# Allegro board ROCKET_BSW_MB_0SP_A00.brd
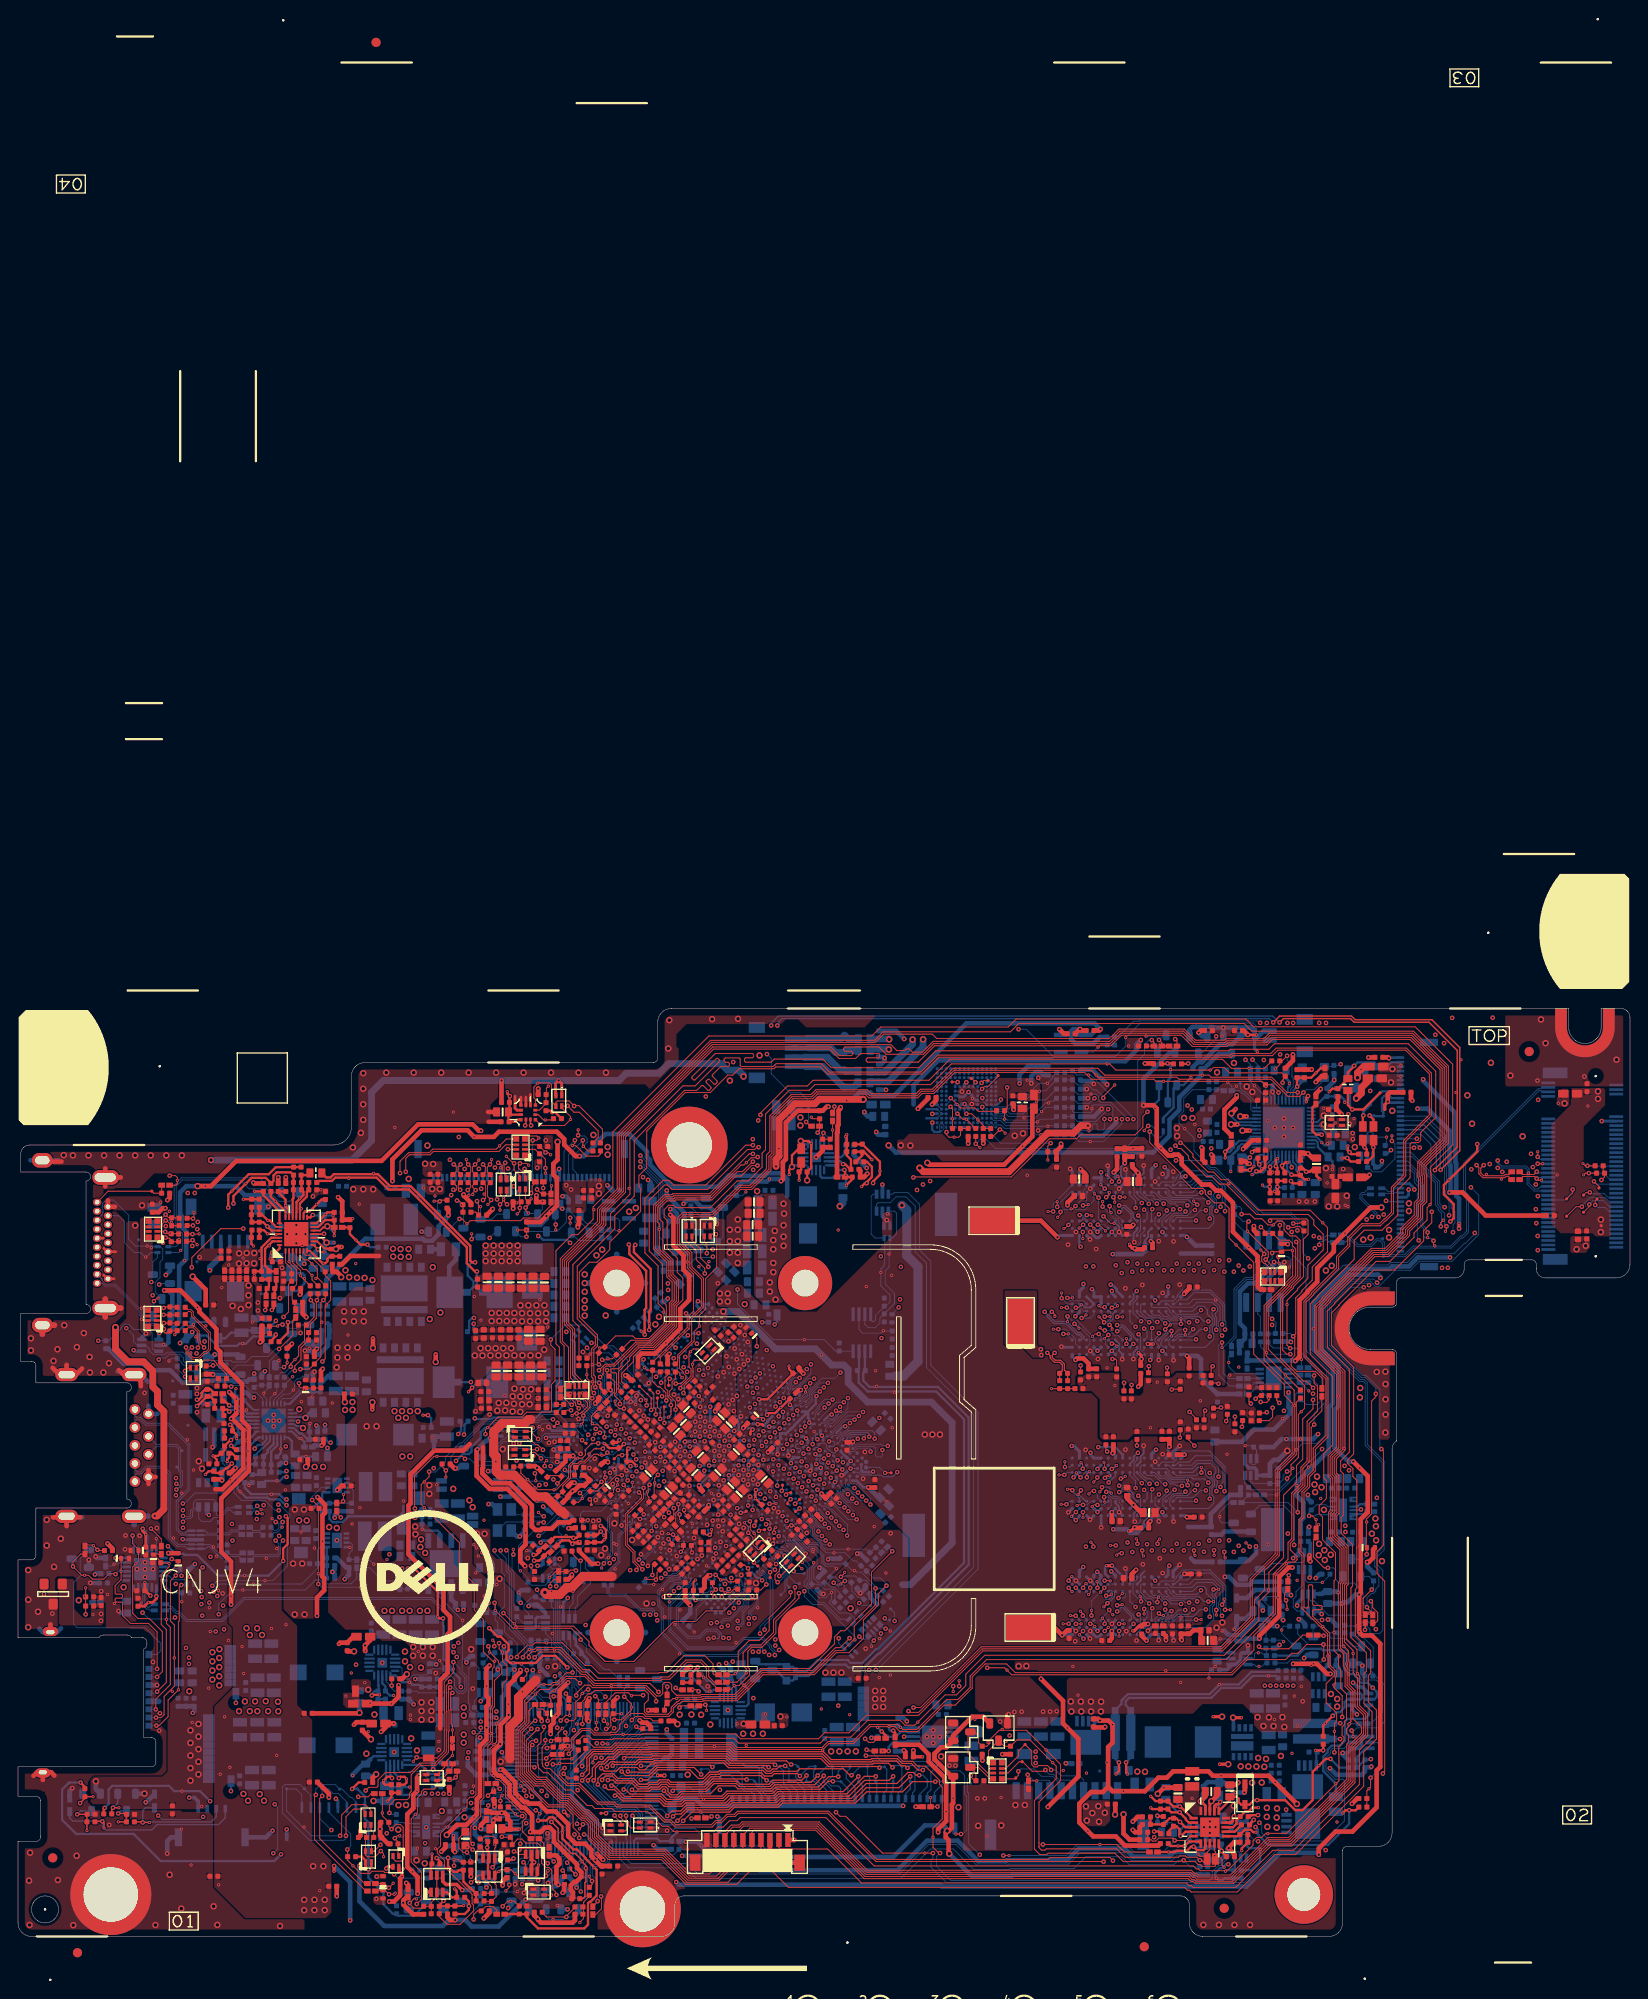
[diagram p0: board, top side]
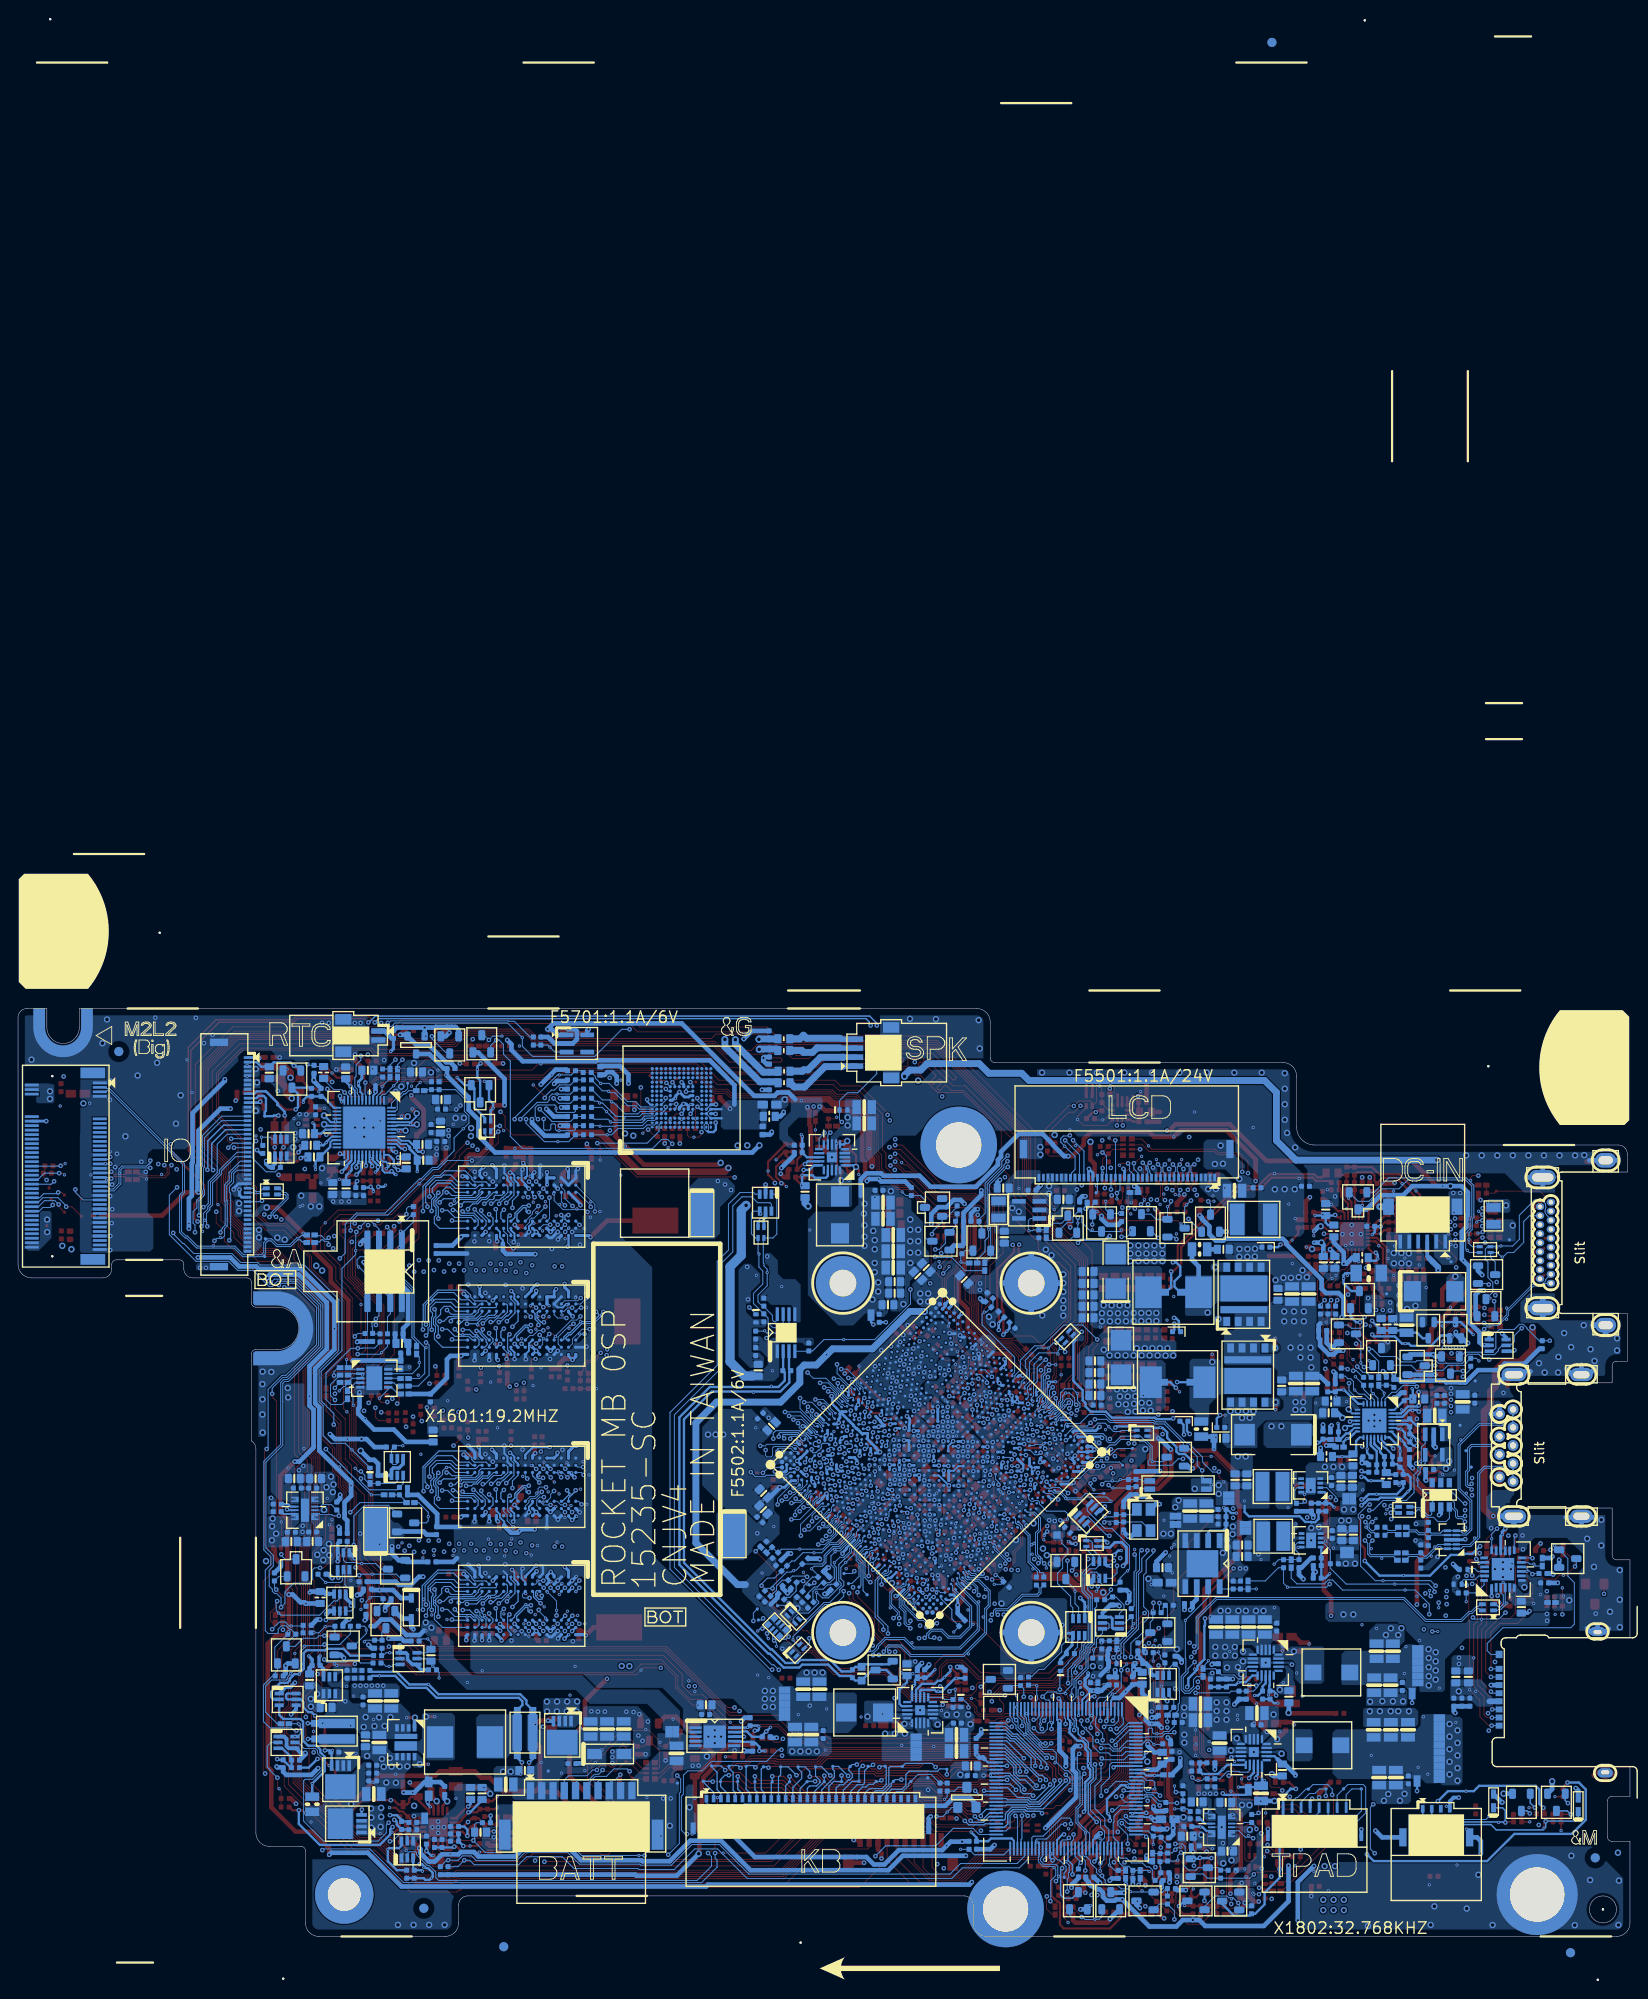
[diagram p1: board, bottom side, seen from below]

Outline 178.9 x 103 mm; copper layers: TOP, L2GND, L3, L4, L5VCC, BOTTOM. Coordinates in mm from the lower left corner of the outline.
Outline path: 0,41.8 0,33.15 8.99,33.15 arc(9.18,33.37) 9.45,33.46 12.15,33.46 arc(12.42,33.37) 12.61,33.15 13.8,33.15 arc(14.15,33.01) 14.3,32.66 14.3,32.38 arc(14.2,32.08) 13.95,31.9 13.95,22.07 14.8,22.07 arc(15.15,21.93) 15.3,21.58 15.3,19.34 arc(15.15,18.99) 14.8,18.85 0,18.85 0,15.55 2,15.55 arc(2.35,15.4) 2.5,15.05 2.5,11.05 arc(2.35,10.7) 2,10.55 0,10.55 0,1.5 arc(0.44,0.44) 1.5,0 71.4,0 arc(72.46,0.44) 72.9,1.5 72.9,3.5 arc(73.19,4.21) 73.9,4.5 129,4.5 arc(129.71,4.21) 130,3.5 130,1.5 arc(130.44,0.44) 131.5,0 145.5,0 arc(146.56,0.44) 147,1.5 147,9.5 arc(147.15,9.85) 147.5,10 151,10 arc(152.06,10.44) 152.5,11.5 152.5,54.13 arc(152.63,54.63) 153,55 153,64.65 arc(152.85,65) 152.5,65.15 150.09,65.15 arc(147.74,67.5) 150.09,69.85 152.5,69.85 arc(152.85,70) 153,70.35 153,72.6 arc(153.15,72.95) 153.5,73.1 159.5,73.1 arc(160.21,73.39) 160.5,74.1 160.5,74.6 arc(160.65,74.95) 161,75.1 168,75.1 arc(168.35,74.95) 168.5,74.6 168.5,74.1 arc(168.79,73.39) 169.5,73.1 177.4,73.1 arc(178.46,73.54) 178.9,74.6 178.9,102 arc(178.61,102.71) 177.9,103 175.7,103 175.7,100.9 arc(173.9,99.1) 172.1,100.9 172.1,103 72.5,103 arc(71.44,102.56) 71,101.5 71,97.5 arc(70.85,97.15) 70.5,97 38.5,97 arc(37.44,96.56) 37,95.5 37,89.85 arc(36.41,88.44) 35,87.85 1.3,87.85 arc(0.59,87.56) 0.3,86.85 0.3,84.85 7.55,84.85 arc(8.05,84.35) 7.55,83.85 7.55,70.15 arc(8.05,69.65) 7.55,69.15 0.3,69.15 0.3,63.85 1.48,63.85 arc(1.83,63.7) 1.98,63.35 1.98,61.45 12.08,61.45 arc(12.58,60.95) 12.08,60.45 12.08,48.55 arc(12.58,48.05) 12.08,47.55 1.98,47.55 1.98,42.3 arc(1.83,41.95) 1.48,41.8 0,41.8 ; 1.5,3 arc(3,4.5) 4.5,3 arc(3,1.5) 1.5,3 ; 7.3,4.65 arc(10.3,7.65) 13.3,4.65 arc(10.3,1.65) 7.3,4.65 ; 66.8,3.05 arc(69.3,5.55) 71.8,3.05 arc(69.3,0.55) 66.8,3.05 ; 72,87.85 arc(74.5,90.35) 77,87.85 arc(74.5,85.35) 72,87.85 ; 140.9,4.65 arc(142.7,6.45) 144.5,4.65 arc(142.7,2.85) 140.9,4.65

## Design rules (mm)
constraint set DEFAULT: min track width 0.127, pair gap 0.102
net group CHARGER_10MIL_VIA_25MIL: nets PWR_CHG_CSON_1 PWR_CHG_CSOP_1
net group CLK-MW: nets PCH_SUSCLK PCH_SUSCLK_KBC
net group COMP_DRAM: nets DRAM_RCOMP_1 SM_RCOMP_0
net group EDP_AUX_CON_N: nets EDP_AUX_CON_N EDP_AUX_CPU_N
net group EDP_AUX_CON_P: nets EDP_AUX_CON_P EDP_AUX_CPU_P
net group EDP_TX_CON_N0: nets EDP_TX_CON_N0 EDP_TX_CPU_N0
net group EDP_TX_CON_N1: nets EDP_TX_CON_N1 EDP_TX_CPU_N1
net group EDP_TX_CON_P0: nets EDP_TX_CON_P0 EDP_TX_CPU_P0
net group EDP_TX_CON_P1: nets EDP_TX_CON_P1 EDP_TX_CPU_P1
net group EMMC_CMD: nets EMMC_CMD EMMC_CMD_R
net group EMMC_DATA_0: nets EMMC_DATA_0 EMMC_DATA_0_R
net group EMMC_DATA_1: nets EMMC_DATA_1 EMMC_DATA_1_R
net group EMMC_DATA_2: nets EMMC_DATA_2 EMMC_DATA_2_R
net group EMMC_DATA_3: nets EMMC_DATA_3 EMMC_DATA_3_R
net group EMMC_DATA_4: nets EMMC_DATA_4 EMMC_DATA_4_R
net group EMMC_DATA_5: nets EMMC_DATA_5 EMMC_DATA_5_R
net group EMMC_DATA_6: nets EMMC_DATA_6 EMMC_DATA_6_R
net group EMMC_DATA_7: nets EMMC_DATA_7 EMMC_DATA_7_R
net group EMMC_RCLK: nets EMMC_RCLK EMMC_RCLK_R
net group HDA-MW: nets HDA_CODEC_RST#_CTRL HDA_SPKR
net group HDA_BITCLK_CODEC: nets HDA_BITCLK_CODEC HDA_BITCLK_CPU
net group HDA_RST#_CODEC: nets HDA_RST#_CODEC HDA_RST#_CPU
net group HDA_SDIN0_CODEC: nets HDA_SDIN0_CODEC HDA_SDIN0_CPU
net group HDA_SDOUT_CODEC: nets HDA_SDOUT_CODEC HDA_SDOUT_CPU
net group HDA_SYNC_CODEC: nets HDA_SYNC_CODEC HDA_SYNC_CPU
net group HDMI_DATA_CON_N0: nets HDMI_DATA_CON_N0 HDMI_DATA_CPU_N0
net group HDMI_DATA_CON_N1: nets HDMI_DATA_CON_N1 HDMI_DATA_CPU_N1
net group HDMI_DATA_CON_N2: nets HDMI_DATA_CON_N2 HDMI_DATA_CPU_N2
net group HDMI_DATA_CON_N3: nets HDMI_DATA_CON_N3 HDMI_DATA_CPU_N3
net group HDMI_DATA_CON_P0: nets HDMI_DATA_CON_P0 HDMI_DATA_CPU_P0
net group HDMI_DATA_CON_P1: nets HDMI_DATA_CON_P1 HDMI_DATA_CPU_P1
net group HDMI_DATA_CON_P2: nets HDMI_DATA_CON_P2 HDMI_DATA_CPU_P2
net group HDMI_DATA_CON_P3: nets HDMI_DATA_CON_P3 HDMI_DATA_CPU_P3
net group INT_SERIRQ: nets INT_SERIRQ LPC_SERIRQ_CPU
net group LPC_AD_CPU_P0: nets LPC_AD_CPU_P0 LPC_AD_CPU_R_P0
net group LPC_AD_CPU_P1: nets LPC_AD_CPU_P1 LPC_AD_CPU_R_P1
net group LPC_AD_CPU_P2: nets LPC_AD_CPU_P2 LPC_AD_CPU_R_P2
net group LPC_AD_CPU_P3: nets LPC_AD_CPU_P3 LPC_AD_CPU_R_P3
net group LPC_CLK_CPU_P0: nets LPC_CLK_CPU_P0 LPC_CLK_LPC
net group LPC_CLK_CPU_P1: nets LPC_CLK_CPU_P1 LPC_CLK_KBC
net group LPC_FRAME#_CPU: nets LPC_FRAME#_CPU LPC_FRAME#_CPU_R
net group PCIE_RX_CPU_N0: nets PCIE_RX_CPU_N0 WLANTX_N3
net group PCIE_RX_CPU_P0: nets PCIE_RX_CPU_P0 WLANTX_P3
net group PCIE_TX_CON_N0: nets PCIE_TX_CON_N0 PCIE_TX_CPU_N0
net group PCIE_TX_CON_P0: nets PCIE_TX_CON_P0 PCIE_TX_CPU_P0
net group POWER_10_VCCTSEN: nets PWR_VCC0_TSEN PWR_VCC0_TSEN1
net group POWER_10_VIA_20: nets PWR_VCC0_CSCOMP PWR_VCC0_CSMP1
net group POWER_12: nets CARD_AV18 SDREG
net group PSID_4M: nets PS_ID PSID_EC
net group SD_MMC_CLK/MS_DATA2: nets SD_MMC_CLK/MS_DATA2 SP5
net group SENSOR: nets GSEN2_INT1 GSEN2_INT2
net group SPI_HOLD_CPU: nets SPI_HOLD_CPU SPI_HOLD_ROM
net group SPI_SI_CPU: nets SPI_SI_CPU SPI_SI_ROM
net group SPI_SO_CPU: nets SPI_SO_CPU SPI_SO_ROM
net group SPI_WP_CPU: nets SPI_WP_CPU SPI_WP_ROM
net group T8: nets VD_IN1 VD_IN1_C
net group THERM_10MIL: nets VD1_EN# VD_OUT1#
net group USB30_TX_CMC_N0: nets USB30_TX_CMC_N0 USB30_TX_CPU_N0
net group USB30_TX_CMC_P0: nets USB30_TX_CMC_P0 USB30_TX_CPU_P0
net group USB_CON_PN0: nets USB_CON_PN0 USB_CPU_PN0
net group USB_CON_PN1: nets USB_CON_PN1 USB_CPU_PN1
net group USB_CON_PN2: nets USB_CON_PN2 USB_CPU_PN2
net group USB_CON_PN4: nets USB_CON_PN4 USB_CPU_PN4
net group USB_CON_PP0: nets USB_CON_PP0 USB_CPU_PP0
net group USB_CON_PP1: nets USB_CON_PP1 USB_CPU_PP1
net group USB_CON_PP2: nets USB_CON_PP2 USB_CPU_PP2
net group USB_CON_PP4: nets USB_CON_PP4 USB_CPU_PP4
net group 3V_5V_10MIL: nets PWR_3D3V_FB PWR_3D3V_VOUT PWR_5V_FB PWR_5V_FB_A PWR_5V_VOUT
net group 3V_5V_20MIL: nets PWR_3D3V_BOOT_A PWR_5V_BOOT_A PWR_5V_VCC
net group BKLT_EDP-MW: nets BKLT_CTRL EC_BRIGHTNESS L_BKLT_CTRL L_BKLT_CTRL_B L_BKLT_CTRL_CPU LCD_BRIGHTNESS LVDS_VDD_EN LVDS_VDD_EN_B LVDS_VDD_EN_CPU LVDS_VDD_EN_R
net group CHARGER_10MIL: nets BOOST_MODE# PWR_CHG_CMPIN_R PWR_CHG_CMPIN_RR PWR_CHG_IFAULT PWR_CHG_ILIM PWR_CHG_IOUT
net group CHARGER_20MIL: nets PWR_CHG_BTST_R
net group CLK_19D2M_CPU-MW: nets ICLKICOMP ICLKRCOMP XTL_19D2M_X1_CPU XTL_19D2M_X2_CPU
net group CLK_CARD: nets 12MHZ_IN
net group CLK_FST_SPI-MW: nets SPI_CLK_CPU_MUX SPI_CLK_KBC SPI_CLK_KBC_MUX SPI_CLK_KBC_R SPI_CLK_ROM_MUX
net group CLK_SVID-MW: nets CPU_VSS2 CPU_VSS16 VIDSCK_CORE VIDSCK_CPU VIDSCK_CPU_R VIDSCK_GFX
net group COMP_10: nets GPIO_RCOMP18 RCOMP_LPC_HVT SDMMC1_RCOMP SDMMC3_RCOMP
net group COMP_HSIC: nets USB_HSIC_RCOMP
net group COMP_MCSI-MW: nets MCSI_COMP
net group COMP_USB: nets USB_RCOMP
net group CPU_SIDE-MW: nets 1D35V_VTT_PWRGD AC_PRESENT_CPU AC_PRESENT_KBC AD_IA CFG0 CFG1 CFG2 CFG3 CFG4 CFG5 CFG6 CFG7 CFG8 COREPWROK DBC_EN DBC_EN_C DBC_EN_R DDR3_DRAM_PWROK DDR3_DRAM_PWROK_D DDR3_VCCA_PWRGD DDR3_VCCA_PWRGD_G DRAM_SEL0 DRAM_SEL1 DRAM_SEL2 ECSMI#_KBC EDM_SOC EDP_HPD_CPU FFS_INT2_CPU GP_CAMERASB00 GP_CAMERASB01 GP_CAMERASB02 GP_CAMERASB03 GP_CAMERASB04 GP_CAMERASB05 GP_CAMERASB06 GP_CAMERASB07 GP_CAMERASB08 GP_CAMERASB09 GP_CAMERASB11 GPIO_ALERT GPIO_SUS0 GPIO_SUS1 GPIO_SUS2 GPIO_SUS3 GPIO_SUS4 H_PROCHOT# HDD_FALL_INT_C HDMI_HPD_G HDMI_PCH_DET# HPD_HDMI_CON INT_TP# INT_TP#_CONN L_BKLT_EN L_BKLT_EN_CPU ME_FWP_SOC ME_UNLOCK# PCU_SMB_ALERT# PEG_CLKREQ0_CPU# PEG_CLKREQ0_D PEG_CLKREQ0_WLAN# PEG_CLKREQ1_CPU# PEG_CLKREQ2_CPU# PEG_CLKREQ3_CPU# PLT_RST# PLT_RST#_CPU_G PLT_RST#_D PLTRST# PLTRST#_CPU PLTRST#_CPU_D PM_PCIE_WAKE# PM_PWRBTN# PM_PWRBTN#_CPU PM_RSMRST# PM_SLP_S0IX# PM_SLP_S3# PM_SLP_S3#_CPU PM_SLP_S3#_CPU_D PM_SLP_S4# PM_SLP_S4#_CPU PM_SLP_S4#_CPU_D PM_SUS_STAT#_CPU PMC_BATLOW# PMC_RSTBTN# PROCHOT#_CPU PROCHOT#_EC PWR_1D35V_PGOOD PWR_GFX_VRHOT# PWR_VCORE_VRHOT# Q3601_2 Q3615_G RSMRST#_KBC RSMRST#_KBC_G RSMRST#_KBC_MUX RSVD_VSS#A3 RTC_INTRUDER RUN_ON# RUN_ON_R SATA_RXN0 SATA_RXN1 SATA_RXP0 SATA_RXP1 SEC_GPIO_SUS8 SEC_GPIO_SUS9 SEC_GPIO_SUS10 SENSOR_HUB_RST#_R SM_DRAMRST# SOC_EXTSMI_N SOC_RUNTIME_SCI# SOC_RUNTIME_SCI#_KBC SPI_CS_CPU_MUX SPI_CS_KBC_MUX SPI_CS_KBC_N0 SPI_CS_KBC_R_N0 SPI_CS_ROM_MUX SPI_SI_KBC SPI_SI_KBC_R SPI_SO_KBC SUS_PWR_ACK_R SUS_PWRDN_ACK SUS_PWRDN_ACK_CPU SYS_PWROK SYS_PWROK_G UART1_CTS UART1_RTS UART1_RX UART1_RXD UART1_TX UART1_TXD USB_OTG_ID USB_VBUSSNS VSS5 XDP_PREQ# XDP_TCK XDP_TDI XDP_TDO XDP_TMS XDP_TRST#
net group DDR3_CHA_CMD-MW: nets M_A_A0 M_A_A1 M_A_A2 M_A_A3 M_A_A4 M_A_A5 M_A_A6 M_A_A7 M_A_A8 M_A_A9 M_A_A10 M_A_A11 M_A_A12 M_A_A13 M_A_A14 M_A_A15 M_A_BS0 M_A_BS1 M_A_BS2 M_A_CAS# M_A_RAS# M_A_WE#
net group DDR3_CHA_CTRL-MW: nets M_A_CKE0 M_A_CS#0 M_A_DIM0_ODT0
net group DDR3_CHA_DATA-MW: nets M_A_DM0 M_A_DM1 M_A_DM2 M_A_DM3 M_A_DM4 M_A_DM5 M_A_DM6 M_A_DM7 M_A_DQ0 M_A_DQ1 M_A_DQ2 M_A_DQ3 M_A_DQ4 M_A_DQ5 M_A_DQ6 M_A_DQ7 M_A_DQ8 M_A_DQ9 M_A_DQ10 M_A_DQ11 M_A_DQ12 M_A_DQ13 M_A_DQ14 M_A_DQ15 M_A_DQ16 M_A_DQ17 M_A_DQ18 M_A_DQ19 M_A_DQ20 M_A_DQ21 M_A_DQ22 M_A_DQ23 M_A_DQ24 M_A_DQ25 M_A_DQ26 M_A_DQ27 M_A_DQ28 M_A_DQ29 M_A_DQ30 M_A_DQ31 M_A_DQ32 M_A_DQ33 M_A_DQ34 M_A_DQ35 M_A_DQ36 M_A_DQ37 M_A_DQ38 M_A_DQ39 M_A_DQ40 M_A_DQ41 M_A_DQ42 M_A_DQ43 M_A_DQ44 M_A_DQ45 M_A_DQ46 M_A_DQ47 M_A_DQ48 M_A_DQ49 M_A_DQ50 M_A_DQ51 M_A_DQ52 M_A_DQ53 M_A_DQ54 M_A_DQ55 M_A_DQ56 M_A_DQ57 M_A_DQ58 M_A_DQ59 M_A_DQ60 M_A_DQ61 M_A_DQ62 M_A_DQ63
net group DDR3L_ZQ: nets VRAM_CH_A_ZQ_1A VRAM_CH_A_ZQ_2A VRAM_CH_A_ZQ_3A VRAM_CH_A_ZQ_4A
net group EMMC_CLK: nets EMMC_CLK EMMC_CLK_L EMMC_CLK_R
net group EMMC_DATA_CMD: nets EMMC_E9 EMMC_E10 EMMC_F10 EMMC_K10 EMMC_RESET# EMMC_RESET#_R EMMC_VDDI
net group GND_100: nets EC_AGND
net group HDMI_DDC-MW: nets HDMI_CLK_CON HDMI_CLK_CPU HDMI_DATA_CON HDMI_DATA_CPU
net group KB: nets KCOL0 KCOL1 KCOL2 KCOL3 KCOL4 KCOL5 KCOL6 KCOL7 KCOL8 KCOL9 KCOL10 KCOL11 KCOL12 KCOL13 KCOL14 KCOL15 KCOL16 KROW0 KROW1 KROW2 KROW3 KROW4 KROW5 KROW6 KROW7
net group LED: nets AMBER_LED_BAT BAT_AMBER BAT_WHITE BATT_WHITE_LED_R# CHG_AMBER_LED_R# D_BAT_AMBER D_BAT_WHITE WHITE_LED_BAT
net group M_A_CLK0: nets M_A_CLK0_L
net group OTHER_4: nets 1D05V_PWRGD 1D5V_S0_EN 1D05V_VNN_EN 1D05V_VNN_PG_G 1D05V_VNN_PWRGD 1D8V_S0_EN 1D8V_S5_PG 1D24V_S5_PG 3D3V_S5_PRIME_EN 3D3V_S5_PRIME_PG 3D3V_S5_PRIME_PG_1 3V_5V_EN 3V_5V_POK 5V_DDC_HDMI1 5V_DDC_HDMI2 AC_IN# AC_IN_KBC# AD_IA_HW AD_IA_HW2 ALERT# ALL_SYS_PWRGD ALS_INT# AMP_MUTE# BAT_IN# BLON_OUT BLON_OUT_C BLUETOOTH_EN CAMERA_DET# CAP_LED CAP_LED# CAP_LED_Q CAP_LED_R# COMBO-GPI DP_HPD0_C DP_HPD0_G E51_RX1 E51_RX2 E51_TX1 E51_TX2 E51_TXD EAPD# ECRST# GFX_PWRGD GSENSOR_CS GSENSOR_SDO H_A20GATE H_RCIN# HALL_KB_DIS# HDMI_IN# IMVP_PWRGD INT_SERIRQ_OE KB_LOOP KBC_BEEP KBC_ON#_GATE KBC_ON#_GATE_L KBC_PECI KBC_PWRBTN# LCD_TST LCD_TST_C LCD_TST_EN LCD_TST_KBC LID_CLOSE# LVDS_VDD_EN_KBC MODEL_ID MODEL_ID_AD NCT3956_OE#_MUX PBAT_PRES1# PCB_VER_AD PQ3802_1 PQ4008_2 PQ4008_6 PQ4405_2 PQ4405_3 PQ4405_5 PQ4405_6 PQ4406_D PQ4406_G PQ4408_C PQ4408_E PSID_DISABLE#_R_C PSL_IN1# PSL_IN2# PSL_OUT# PURE_HW_SHUTDOWN# PWR_1D05V_PWR_EN PWR_1D8V_S5_EN PWR_1D15V_PG PWR_1D15V_S5_EN PWR_1D24V_EN PWR_1D35V_EN PWR_3D3V_EN PWR_3D3V_EN1 PWR_3V_PG PWR_5V_EN1 PWR_5V_PG RTC_DET# SD_CD# SD_CD#_CARD SD_WP#/MS_DATA1_C SENSOR_KB_DIS SIO_SLP_S4 SLEEVE_CTRL SUSPWRDNACK_SOC_EC SYS_PRES1# T_CRIT# THERM_SYS_SHDN# TOUCH_PANEL_EN TP_DISABLE# TP_DISABLE#_R TP_ON# TP_ON#_GATE USB_OC#0 USB_OC#1 USB_PWR_EN# VOL_DOWN# VOL_UP# WIFI_RF_EN
net group OTHER_6: nets S5_ENABLE
net group OTHER_10: nets KBC_VBKUP M_VREF_DQ_DIM0 V_SM_VREF_CNT
net group OTHER_12: nets CPVEE LDO1_CAP LDO2_CAP LDO3_CAP
net group P27_AUDIO_40M: nets AUD_SPK_L+ AUD_SPK_L+_C AUD_SPK_L- AUD_SPK_L-_C AUD_SPK_R+ AUD_SPK_R+_C AUD_SPK_R- AUD_SPK_R-_C
net group P27_AUDIO_ANALOG: nets AUD_HP1_JACK_L AUD_HP1_JACK_L1 AUD_HP1_JACK_R AUD_HP1_JACK_R1 AUD_PC_BEEP AUD_PC_BEEP_C AUD_PORTA_L_R_B AUD_PORTA_R_R_B AUD_SENSE AUD_SENSE_A AUD_VREF CBN CBP HDA_SPKR_R JACK_PLUG KBC_BEEP_R LINE1-L_C LINE1-L_R LINE1_L LINE1_R LINE1_VREFO_L LINE1_VREFO_R
net group POWER_8: nets Q6204_S
net group POWER_10: nets 1D05V_PWR_BS 1D05V_PWR_BS_R 1D05V_PWR_BYP 1D05V_PWR_FB 1D05V_PWR_FBH 1D05V_PWR_FBL 1D05V_PWR_LDO 3D3V_GSEN2 3D3V_S0_CT 5V_PWR_2 5V_S0_CT +3V_1D5V_AVDD +3V_AVDD BATT_WHITE_LED# CHG_AMBER_LED# CPVREF DVDD_1D5V MIC_CAP PU4902_S5 PU4902_VCNTL PWR_1D05V_PWR_ILIM PWR_1D8V_FB PWR_1D15V_FB PWR_1D24V_FB\ PWR_1D35V_BYP PWR_1D35V_IMAX PWR_1D35V_LDO_P5 PWR_1D35V_VFB PWR_3D3V_EN2 PWR_3D3V_FB2 PWR_5V_EN2 PWR_5V_LDO PWR_CHG_ACDET PWR_CHG_ACN PWR_CHG_ACOK PWR_CHG_ACP PWR_CHG_BTST PWR_CHG_CMPIN PWR_CHG_REGN PWR_VCC0_COMP PWR_VCC0_COMP1 PWR_VCC0_COMP2 PWR_VCC0_DIFFOUT PWR_VCC0_FB PWR_VCC0_ILIM PWR_VCC0_IMAX PWR_VCC0_PVCC PWR_VCC0_ROSC PWR_VCC0_VBOOT/ADDR PWR_VCC0_VCC PWR_VCC0_VRMP PWR_VGG_COMP PWR_VGG_COMP1 PWR_VGG_COMP2 PWR_VGG_CSCOMP PWR_VGG_CSMP1 PWR_VGG_DIFFOUT PWR_VGG_FB PWR_VGG_ILIM PWR_VGG_IMAX PWR_VGG_IOUT PWR_VGG_PVCC PWR_VGG_ROSC PWR_VGG_TSEN PWR_VGG_TSEN1 PWR_VGG_VBOOT/ADDR PWR_VGG_VCC PWR_VGG_VRMP Q6205_D Q6206_D TP_VDD VCC_VCORE1_SENSE VSS_VCORE1_SENSE VSS_VNN_SENSE VTT_CT_1D8VC VTT_CT_3D3V_S5_PRIME VTT_EN
net group POWER_10_VCCI: nets PWR_VCC0_IOUT
net group POWER_10_VIA: nets AD+_G_1 AD+_G_2 DC_IN_D PWR_CHG_SRN PWR_CHG_SRP
net group POWER_10M_POWER: nets AD_OFF_L AD_OFF_R PQ4209_D PWR_CHG_AD_OFF PWR_CHG_AD_OFF_R PWR_CHG_CMPOUT
net group POWER_20: nets 0D675V_S0_DISCHG 1D5V_BRI_S0 1D5V_DIS_Q +RTC_PWR +VCHGR_R BOOST_MON_1 EC_AVCC EC_VTT KBC_VCORF PD4403_A PD4403_K PU4401_6 PWR_GFX_SNUB PWR_VCORE_SNUB
net group POWER_40: nets PWR_VGG_BT VREF_DQ VREF_DQ_R1203
net group POWER_40_ULP: nets PWR_CHG_HIDRV
net group POWER_600_VIA: nets DCBATOUT_R
net group RTC-MW: nets BVCCRTC_EXTPAD
net group SMBUS_CLK-MW: nets BAT_SCL DMIC_CLK DMIC_CLK_C DMIC_CLK_R NCT_CLK PBAT_SMBCLK1 PWR_CHG_BAT_SCL SENSOR_I2C_SCL SENSOR_I2C_SCL_ALS SIO_I2C5_CLK SMB_CLK SML1_CLK TP_CLK TP_CLK_C TP_I2C_CLK TP_I2C_CLK_D TPCLK
net group SMBUS_DAT-MW: nets BAT_SDA DMIC_DATA DMIC_DATA_C DMIC_DATA_R NCT_DATA PBAT_SMBDAT1 PWR_CHG_BAT_SDA SENSOR_I2C_SDA SENSOR_I2C_SDA_ALS SIO_I2C5_DATA SMB_DATA SML1_DATA TP_DAT TP_DATA_C TP_I2C_DATA TP_I2C_DATA_D TPDATA
net group SPI_CLK_CPU: nets SPI_CLK_CPU SPI_CLK_ROM SPI_CLK_ROM_R
net group SPI_CS_CPU_N0: nets SPI_CS_CPU_N0 SPI_CS_ROM_N0 SPI_CS_ROM_N0_R
net group SVID-MW: nets VIDALERT#_CORE VIDALERT#_CPU VIDALERT#_CPU_R VIDALERT#_GFX VIDSOUT_CORE VIDSOUT_CPU VIDSOUT_CPU_R VIDSOUT_GFX
net group USB30_RX_CON_N0: nets USB30_RX_CPU_N0
net group USB30_RX_CON_P0: nets USB30_RX_CPU_P0
net group USB_CON_PN3: nets USB_CON_PN3
net group USB_CON_PP3: nets USB_CON_PP3
net group XTAL-MW: nets RTC_TEST# RTCRST_ON XTL_32D768K_X1_CPU XTL_32D768K_X2_CPU

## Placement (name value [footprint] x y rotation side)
AFTP2901  AFTE14P-GP  [AFTE14P-75]  91.73 100.03 270 bottom
AFTP2902  AFTE14P-GP  [AFTE14P-75]  91.73 98.13 270 bottom
AFTP2903  AFTE14P-GP  [AFTE14P-75]  91.71 96.19 270 bottom
AFTP2904  AFTE14P-GP  [AFTE14P-75]  91.72 94.29 270 bottom
AFTP2906  AFTE14P-GP  [AFTE14P-75]  151.53 91.06 0 bottom
AFTP2907  AFTE14P-GP  [AFTE14P-75]  150.09 92.33 180 bottom
AFTP2908  AFTE14P-GP  [AFTE14P-75]  151.68 91.81 0 top
AFTP2909  AFTE14P-GP  [AFTE14P-75]  151.16 93.65 0 top
AFTP3401  AFTE14P-GP  [AFTE14P-75]  18.86 56.73 90 bottom
AFTP3402  AFTE14P-GP  [AFTE14P-75]  18.19 53.92 270 bottom
AFTP3403  AFTE14P-GP  [AFTE14P-75]  17.62 52.09 270 bottom
AFTP3404  AFTE14P-GP  [AFTE14P-75]  17.18 61.66 90 bottom
AFTP4201  AFTE14P-GP  [AFTE14P-75]  27.01 71.33 180 bottom
AFTP4202  AFTE14P-GP  [AFTE14P-75]  21.9 74.89 180 bottom
AFTP4203  AFTE14P-GP  [AFTE14P-75]  19.86 74.89 180 bottom
AFTP4301  AFTE14P-GP  [AFTE14P-75]  110.73 17.58 0 top
AFTP4302  AFTE14P-GP  [AFTE14P-75]  111.43 19.4 0 top
AFTP4303  AFTE14P-GP  [AFTE14P-75]  111.77 21.3 0 top
AFTP4304  AFTE14P-GP  [AFTE14P-75]  120.05 18.36 180 bottom
AFTP4305  AFTE14P-GP  [AFTE14P-75]  105.72 17.02 180 bottom
AFTP5402  AFTE14P-GP  [AFTE14P-75]  13.38 77.33 180 bottom
AFTP6101  AFTE14P-GP  [AFTE14P-75]  175.71 78.9 270 top
AFTP6102  AFTE14P-GP  [AFTE14P-75]  171.86 81.87 270 top
AFTP6104  AFTE14P-GP  [AFTE14P-75]  173.75 80.38 270 top
AFTP6105  AFTE14P-GP  [AFTE14P-75]  173.75 82.29 270 top
AFTP6110  AFTE14P-GP  [AFTE14P-75]  171.87 79.94 270 top
AFTP6111  AFTE14P-GP  [AFTE14P-75]  151.53 75.47 0 bottom
AFTP6113  AFTE14P-GP  [AFTE14P-75]  151.45 77.45 0 bottom
AFTP6201  AFTE14P-GP  [AFTE14P-75]  102.84 17.22 180 bottom
AFTP6202  AFTE14P-GP  [AFTE14P-75]  101.93 18.93 180 bottom
AFTP6203  AFTE14P-GP  [AFTE14P-75]  100.93 17.19 180 bottom
AFTP6204  AFTE14P-GP  [AFTE14P-75]  100 18.88 180 bottom
AFTP6205  AFTE14P-GP  [AFTE14P-75]  99.02 17.2 180 bottom
AFTP6206  AFTE14P-GP  [AFTE14P-75]  98.1 18.88 180 bottom
AFTP6207  AFTE14P-GP  [AFTE14P-75]  97.12 17.18 180 bottom
AFTP6208  AFTE14P-GP  [AFTE14P-75]  96.16 18.83 180 bottom
AFTP6209  AFTE14P-GP  [AFTE14P-75]  95.2 17.17 180 bottom
AFTP6210  AFTE14P-GP  [AFTE14P-75]  94.26 18.83 180 bottom
AFTP6211  AFTE14P-GP  [AFTE14P-75]  93.27 17.18 180 bottom
AFTP6212  AFTE14P-GP  [AFTE14P-75]  92.33 18.83 180 bottom
AFTP6213  AFTE14P-GP  [AFTE14P-75]  91.33 17.18 180 bottom
AFTP6214  AFTE14P-GP  [AFTE14P-75]  90.39 18.83 180 bottom
AFTP6215  AFTE14P-GP  [AFTE14P-75]  89.42 17.18 180 bottom
AFTP6216  AFTE14P-GP  [AFTE14P-75]  88.47 18.87 180 bottom
AFTP6217  AFTE14P-GP  [AFTE14P-75]  87.5 17.2 180 bottom
AFTP6218  AFTE14P-GP  [AFTE14P-75]  86.54 18.86 180 bottom
AFTP6220  AFTE14P-GP  [AFTE14P-75]  84.56 18.88 180 bottom
AFTP6221  AFTE14P-GP  [AFTE14P-75]  83.66 17.2 180 bottom
AFTP6222  AFTE14P-GP  [AFTE14P-75]  82.67 18.89 180 bottom
AFTP6223  AFTE14P-GP  [AFTE14P-75]  80.76 18.87 180 bottom
AFTP6224  AFTE14P-GP  [AFTE14P-75]  81.75 17.22 180 bottom
AFTP6225  AFTE14P-GP  [AFTE14P-75]  75.81 18.55 180 bottom
AFTP6226  AFTE14P-GP  [AFTE14P-75]  77.94 17.59 180 bottom
AFTP6227  AFTE14P-GP  [AFTE14P-75]  85.57 17.21 180 bottom
AFTP6228  AFTE14P-GP  [AFTE14P-75]  37.66 16.38 270 bottom
AFTP6229  AFTE14P-GP  [AFTE14P-75]  29.82 16.37 180 bottom
AFTP6230  AFTE14P-GP  [AFTE14P-75]  31.79 16.39 270 bottom
AFTP6231  AFTE14P-GP  [AFTE14P-75]  35.68 16.35 270 bottom
AFTP6232  AFTE14P-GP  [AFTE14P-75]  33.74 16.37 270 bottom
AFTP6233  AFTE14P-GP  [AFTE14P-75]  79.81 17.2 180 bottom
BATT1  ACES-CON10-10-GP-U  [88231-1001-LP]  116.4 11.3 180 bottom
C1001  SC1U10V2KX-1GP  [C402H22]  69.94 55.72 135 top
C1002  SC1U10V2KX-1GP  [C402H22]  71.28 55.3 225 top
C1003  SC1U10V2KX-1GP  [C402H22]  77.98 47.51 45 top
C1004  SC1U10V2KX-1GP  [C402H22]  72.57 52.35 135 top
C1005  SC1U10V2KX-1GP  [C402H22]  75.26 47.5 315 top
C1006  SC1U10V2KX-1GP  [C402H22]  78.55 48.1 45 top
C1007  SC1U10V2KX-1GP  [C402H22]  70.37 54.27 45 top
C1008  SC1U10V2KX-1GP  [C402H22]  72.68 53.61 315 top
C1013  SC1U10V2KX-1GP  [C402H22]  77.44 59.29 225 top
C1015  SC1U10V2KX-1GP  [C402H22]  68.21 57.44 135 top
C1016  SC1U10V2KX-1GP  [C402H22]  74.14 48.7 315 top
C1017  SC1U10V2KX-1GP  [C402H22]  64.56 57.44 225 top
C1018  SC1U10V2KX-1GP  [C402H22]  73.54 51.01 135 top
C1019  SC1U10V2KX-1GP  [C402H22]  64.41 52.1 315 top
C1020  SC1U10V2KX-1GP  [C402H22]  68.79 56.87 135 top
C1021  SC1U10V2KX-1GP  [C402H22]  74.12 50.44 135 top
C1022  SC1U10V2KX-1GP  [C402H22]  65.93 58.17 225 top
C1023  SC1U10V2KX-1GP  [C402H22]  67.64 58.02 135 top
C1024  SC1U10V2KX-1GP  [C402H22]  70.93 56.8 225 top
C1025  SC1U10V2KX-1GP  [C402H22]  72.11 54.19 315 top
C1026  SC1U10V2KX-1GP  [C402H22]  77.67 66.98 225 top
C1027  SC4D7U6D3V2MX-GP-U  [C402-TO0D2H26]  51.81 59.51 270 top
C1028  SC1U10V2KX-1GP  [C402H22]  79.15 67.36 135 top
C1029  SC4D7U6D3V2MX-GP-U  [C402-TO0D2H26]  58.18 58.75 90 top
C1030  SC4D7U6D3V2MX-GP-U  [C402-TO0D2H26]  51.53 61.45 270 top
C1032  SC1U10V2KX-1GP  [C402H22]  58.18 59.72 90 top
C1033  SC1U10V2KX-1GP  [C402H22]  51.81 60.48 270 top
C1034  SC1U10V2KX-1GP  [C402H22]  81.28 53.19 225 top
C1035  SC1U10V2KX-1GP  [C402H22]  90.52 48.94 225 top
C1036  SC1U10V2KX-1GP  [C402H22]  58.18 60.68 90 top
C1037  SC1U10V2KX-1GP  [C402H22]  87.02 46.42 315 top
C1038  SC1U10V2KX-1GP  [C402H22]  89.94 48.34 225 top
C1039  SC1U10V2KX-1GP  [C402H22]  87.61 45.84 315 top
C1047  SC1U10V2KX-1GP  [C402H22]  79.73 66.78 135 top
C1049  SC1U10V2KX-1GP  [C402H22]  88.36 47.13 45 top
C1050  SC1U10V2KX-1GP  [C402H22]  73.17 48.92 315 top
C1056  SC1U10V2KX-1GP  [C402H22]  74.69 48.07 315 top
C1057  SC1U10V2KX-1GP  [C402H22]  73.7 52.34 315 top
C1101  SC1U10V2KX-1GP  [C402H22]  95.1 50.27 0 top
C1102  SC1U10V2KX-1GP  [C402H22]  68.5 62.05 315 top
C1103  SC1U10V2KX-1GP  [C402H22]  61.58 56.28 180 top
C1104  SC1U10V2KX-1GP  [C402H22]  68.53 44.7 225 top
C1105  SC1U10V2KX-1GP  [C402H22]  69.13 45.3 225 top
C1106  SC1U10V2KX-1GP  [C402H22]  74.03 38.83 0 top
C1107  SC1U10V2KX-1GP  [C402H22]  79.63 42.6 45 top
C1108  SC1U10V2KX-1GP  [C402H22]  79.39 46.17 135 top
C1109  SC1U10V2KX-1GP  [C402H22]  79.34 44.87 135 top
C1110  SC1U10V2KX-1GP  [C402H22]  75.35 60.71 315 top
C1111  SC1U10V2KX-1GP  [C402H22]  76.76 60.7 135 top
C1112  SC1U10V2KX-1GP  [C402H22]  79.78 55.45 315 top
C1113  SC1U10V2KX-1GP  [C402H22]  74.78 59.5 225 top
C1114  SC1U10V2KX-1GP  [C402H22]  74.79 61.34 315 top
C1115  SC1U10V2KX-1GP  [C402H22]  66.36 47.29 180 top
C1116  SC1U10V2KX-1GP  [C402H22]  74.55 41.72 225 top
C1117  SC1U10V2KX-1GP  [C402H22]  79.04 42.01 45 top
C1121  SC1U10V2KX-1GP  [C402H22]  69.74 43.48 45 top
C1125  SC1U10V2KX-1GP  [C402H22]  69.36 56.29 135 top
C1126  SC1U10V2KX-1GP  [C402H22]  61.01 54.59 0 top
C1127  SC1U10V2KX-1GP  [C402H22]  60.2 54.59 0 top
C1128  SC1U10V2KX-1GP  [C402H22]  73.97 41.14 225 top
C1129  SC1U10V2KX-1GP  [C402H22]  76.22 42.92 270 top
C1130  SC1U10V2KX-1GP  [C402H22]  70.33 44.06 45 top
C1131  SC1U10V2KX-1GP  [C402H22]  76.25 49.78 135 top
C1132  SC1U10V2KX-1GP  [C402H22]  60.31 53.32 270 top
C1133  SC1U10V2KX-1GP  [C402H22]  60.73 56.3 180 top
C1134  SC1U10V2KX-1GP  [C402H22]  77.88 40.84 45 top
C1137  SC1U10V2KX-1GP  [C402H22]  76.22 43.74 270 top
C1138  SC1U10V2KX-1GP  [C402H22]  80.52 43.69 135 top
C1143  SC1U10V2KX-1GP  [C402H22]  92 54.42 180 top
C1144  SC1U10V2KX-1GP  [C402H22]  84 54.51 315 top
C1147  SC1U10V2KX-1GP  [C402H22]  73.38 40.55 225 top
C1148  SC1U10V2KX-1GP  [C402H22]  79.92 44.29 135 top
C1149  SC1U10V2KX-1GP  [C402H22]  75.85 46.9 315 top
C1150  SC1U10V2KX-1GP  [C402H22]  78.46 41.43 45 top
C1201  SCD1U16V2KX-3GP  [C402H22]  126.67 33.63 90 top
C1202  SCD2P50V2AN-LGP  [C402H25]  116.05 62.51 270 top
C1203  SC10U6D3V3MX-GP  [C603H38]  125.54 47.04 270 top
C1204  SC10U6D3V2MX-GP-U  [C402-TO0D2H28]  123.15 39.77 90 top
C1205  SC10U6D3V2MX-GP-U  [C402-TO0D2H28]  117.68 82.2 270 top
C1206  SC10U6D3V3MX-GP  [C603H38]  117.78 84.08 90 top
C1207  SC10U6D3V2MX-GP-U  [C402-TO0D2H28]  123.1 49.37 0 top
C1208  SCD1U16V2KX-3GP  [C402H22]  117.75 60.81 270 top
C1209  SC1U10V2KX-1GP  [C402H22]  123.05 78.37 180 top
C1210  SC1U10V2KX-1GP  [C402H22]  116.66 33.52 180 top
C1211  SC1U10V2KX-1GP  [C402H22]  128.19 53.47 90 top
C1212  SC1U10V2KX-1GP  [C402H22]  120.71 32.84 90 top
C1213  SCD1U16V2KX-3GP  [C402H22]  123.66 86.12 0 top
C1214  SC1U10V2KX-1GP  [C402H22]  118.83 62.56 180 top
C1215  SC1U10V2KX-1GP  [C402H22]  127.79 55.62 0 top
C1216  SC1U10V2KX-1GP  [C402H22]  129.97 62.66 180 top
C1217  SC1U10V2KX-1GP  [C402H22]  121.57 55.02 0 top
C1219  SC10U6D3V3MX-GP  [C603H38]  132.03 32.84 270 top
C1220  SC10U6D3V2MX-GP-U  [C402-TO0D2H28]  131.72 33.99 270 top
C1221  SC10U6D3V3MX-GP  [C603H38]  123.73 83.8 90 top
C1222  SC10U6D3V3MX-GP  [C603H38]  132.83 55.55 180 bottom
C1223  SC10U6D3V2MX-GP-U  [C402-TO0D2H28]  121.87 46.1 270 top
C1601  SC3D3P50V2CN-GP  [C402H22]  56.19 47.25 0 bottom
C1602  SC3D3P50V2CN-GP  [C402H22]  56.19 45.56 180 bottom
C1801  SC22P50V2GN-GP  [C402H22]  57.77 32.37 180 bottom
C1802  SC1U10V2KX-1GP  [C402H22]  62.31 45.37 270 top
C1803  SC1U10V2KX-1GP  [C402H22]  58.42 51.3 225 top
C1806  SC3D9P50V2CN-1GP  [C402H22]  54.83 51.18 0 bottom
C1807  SC3D9P50V2CN-1GP  [C402H22]  54.83 49.49 180 bottom
C1810  SCD1U16V2KX-3GP  [C402H22]  65.45 48.68 135 top
C1811  SCD1U16V2KX-3GP  [C402H22]  71.02 71.15 315 bottom
C1910  SC22P50V2JN-4GP  [C402H22]  72.1 63.1 180 top
C1915  SCD1U16V2KX-3GP  [C402H22]  65.88 39.45 180 bottom
C1916  SCD1U16V2KX-3GP  [C402H22]  65.05 39.46 180 bottom
C2401  SC22P50V2JN-4GP  [C402H22]  50.13 23.75 90 bottom
C2414  SC2D2U10V3KX-1GP  [C603H36]  73.1 18.93 270 bottom
C2416  SC2D2U10V3KX-1GP  [C603H36]  53.03 11.95 90 top
C2417  SCD1U16V2KX-3GP  [C402H22]  52.04 11.46 0 bottom
C2428  SCD1U16V2KX-3GP  [C402H22]  54.39 10.19 90 top
C2429  SCD1U16V2KX-3GP  [C402H22]  66.11 7.81 90 top
C2430  SCD1U16V2KX-3GP  [C402H22]  63.16 25.17 180 top
C2431  SCD1U16V2KX-3GP  [C402H22]  50.82 20.1 0 bottom
C2432  SCD1U16V2KX-3GP  [C402H22]  55.21 28.38 0 bottom
C2433  SC2D2U10V3KX-1GP  [C603H36]  54.14 28.66 0 bottom
C2436  SCD1U16V2KX-3GP  [C402H22]  53.89 13.05 90 top
C2438  SCD1U16V2KX-3GP  [C402H22]  54.64 11.46 0 top
C2439  SCD1U16V2KX-3GP  [C402H22]  59.94 6.58 90 bottom
C2440  SCD1U16V2KX-3GP  [C402H22]  73.1 17.86 270 bottom
C2441  SCD1U16V2KX-3GP  [C402H22]  64.82 7.36 0 top
C2442  SCD1U16V2KX-3GP  [C402H22]  57.73 2.69 270 top
C2443  SC1U10V2KX-1GP  [C402H22]  72.57 21.53 0 bottom
C2444  SC1U10V2KX-1GP  [C402H22]  50.89 5.31 90 bottom
C2445  SCD1U16V2KX-3GP  [C402H22]  54.5 30.3 270 bottom
C2446  SCD1U16V2KX-3GP  [C402H22]  52.34 24.98 180 bottom
C2447  SCD1U16V2KX-3GP  [C402H22]  59.88 27.73 0 bottom
C2501  SCD1U16V2KX-3GP  [C402H22]  136.61 66.89 90 bottom
C2502  SC10U6D3V3MX-GP  [C603H38]  136.29 65.82 90 bottom
C2505  SCD1U16V2KX-3GP  [C402H22]  135.99 64.76 90 bottom
C2601  SCD1U16V2KX-3GP  [C402H22]  97.03 64.92 180 bottom
C2602  SC10U6D3V3MX-GP  [C603H38]  96.75 62.84 0 bottom
C2604  SC470P50V2KX-3GP  [C402H22]  86.29 29.16 0 bottom
C2605  SC2200P50V2KX-2GP  [C402H22]  93.58 62.8 90 bottom
C2606  SCD1U16V2KX-3GP  [C402H22]  72.69 79.38 270 bottom
C2612  SCD1U16V2KX-3GP  [C402H22]  51.32 8.82 0 bottom
C2613  SC100P50V2JN-3GP  [C402H22]  52.15 8.75 0 bottom
C2701  SC4D7U6D3V3KX-GP  [C603H36]  135.82 85.87 0 bottom
C2702  SC10U6D3V3MX-GP  [C603H38]  144.12 85.74 0 top
C2703  SC1U10V2KX-1GP  [C402H22]  137.61 86.84 180 top
C2704  SC1U10V2KX-1GP  [C402H22]  138.44 86.84 0 top
C2705  SC2D2U10V3KX-1GP  [C603H36]  142.49 83.03 0 bottom
C2706  SC4D7U6D3V3KX-GP  [C603H36]  132.01 89.84 180 bottom
C2707  SCD1U16V2KX-3GP  [C402H22]  133.07 89.69 180 bottom
C2708  SC4D7U6D3V3KX-GP  [C603H36]  131.9 92.89 90 bottom
C2709  SCD1U16V2KX-3GP  [C402H22]  131.9 91.83 90 bottom
C2710  SCD1U16V2KX-3GP  [C402H22]  146.27 84.36 90 top
C2711  SC4D7U6D3V3KX-GP  [C603H36]  143.97 83.02 180 bottom
C2712  SC10U6D3V3MX-GP  [C603H38]  133.93 86.16 270 bottom
C2713  SC10U6D3V3MX-GP  [C603H38]  146.66 89.11 270 bottom
C2714  SC10U6D3V3MX-GP  [C603H38]  142.54 95.86 180 bottom
C2715  SC4D7U6D3V3KX-GP  [C603H36]  134.01 87.91 90 bottom
C2716  SC4D7U6D3V3KX-GP  [C603H36]  134.68 95.95 90 bottom
C2717  SCD1U16V2KX-3GP  [C402H22]  138.01 92.82 90 top
C2718  SC4D7U6D3V3KX-GP  [C603H36]  140.08 96.14 90 bottom
C2719  SCD1U16V2KX-3GP  [C402H22]  142.77 95.77 180 top
C2720  SCD1U16V2KX-3GP  [C402H22]  128.68 96.85 90 top
C2721  SCD1U16V2KX-3GP  [C402H22]  141.94 95.77 0 top
C2723  SC22P50V2JN-4GP  [C402H22]  138.44 95.84 0 bottom
C2901  SC1U10V2KX-1GP  [C402H22]  150.22 85.37 270 bottom
C2902  SC10U6D3V3MX-GP  [C603H38]  151.01 95.88 0 bottom
C2907  SC10U6D3V3MX-GP  [C603H38]  146.06 86.52 270 bottom
C2908  SC10U6D3V3MX-GP  [C603H38]  146.41 87.82 270 bottom
C3301  SCD1U16V2KX-3GP  [C402H22]  19.55 26 180 bottom
C3302  SCD1U16V2KX-3GP  [C402H22]  18.66 26 180 bottom
C3303  SCD01U16V2KX-3GP  [C402H22]  17.77 26 180 bottom
C3304  SC4D7U6D3V3KX-GP  [C603H36]  17.93 28.81 0 bottom
C3305  SC10U6D3V3KX-GP  [C603H38]  19.33 28.81 0 bottom
C3306  SCD1U16V2KX-3GP  [C402H22]  9.47 39.24 90 bottom
C3307  SC4D7U6D3V3KX-GP  [C603H36]  12.06 36.55 180 bottom
C3308  SC1U10V2KX-1GP  [C402H22]  13.31 37.1 0 top
C3309  SC1U10V2KX-1GP  [C402H22]  14.17 42.78 180 top
C3310  SCD1U10V2KX-5GP  [C402H22]  18.62 38.13 270 bottom
C3505  SCD1U16V2KX-3GP  [C402H22]  27.64 45.42 90 bottom
C3506  SCD1U16V2KX-3GP  [C402H22]  27.64 44.53 90 bottom
C3508  SC1P50V2CN-1GP  [C402H22]  22.38 45.52 0 bottom
C3509  SC1P50V2CN-1GP  [C402H22]  22.38 43.82 180 bottom
C3510  SC1P50V2CN-1GP  [C402H22]  23.22 43.03 0 bottom
C3511  SC1P50V2CN-1GP  [C402H22]  23.22 41.33 180 bottom
C3601  SC22U6D3V5MX-2GP  [C805H58]  18.57 59.34 0 bottom
C3602  SC22U6D3V5MX-2GP  [C805H58]  21.67 57.81 270 bottom
C3606  SCD1U16V2KX-3GP  [C402H22]  22.24 51.82 270 bottom
C3608  SCD1U16V2KX-3GP  [C402H22]  21.44 59.62 0 bottom
C3609  SC1U10V2KX-1GP  [C402H22]  17.22 59.63 0 bottom
C4001  SC1KP50V2KX-1GP  [C402H22]  150.12 47.98 270 bottom
C4002  SCD1U16V2KX-3GP  [C402H22]  49.61 16.28 0 bottom
C4003  SC10U6D3V3MX-GP  [C603H38]  148.56 43.83 90 bottom
C4004  SC470P50V2KX-3GP  [C402H22]  150.13 47.15 270 bottom
C4005  SC10U6D3V3MX-GP  [C603H38]  148.23 50.83 90 bottom
C4011  SC10U6D3V3MX-GP  [C603H38]  48.02 14.93 270 bottom
C4012  SC10U6D3V3MX-GP  [C603H38]  49.13 11.12 270 bottom
C4037  SC10U6D3V3MX-GP  [C603H38]  146.2 43.83 270 bottom
C4038  SC10U6D3V3MX-GP  [C603H38]  145.87 50.83 270 bottom
C4039  SC10U6D3V3MX-GP  [C603H38]  44.66 9.47 270 bottom
C4041  SC330P50V2KX-3GP  [C402H22]  49.07 12.19 270 bottom
C4042  SC10U6D3V3MX-GP  [C603H38]  44.86 14.87 270 bottom
C4043  SC330P50V2KX-3GP  [C402H22]  48.37 13.06 270 bottom
C4046  SCD1U16V2KX-3GP  [C402H22]  41.73 10.27 270 top
C4050  SCD1U16V2KX-3GP  [C402H22]  40.71 12.67 270 top
C4051  SCD1U16V2KX-3GP  [C402H22]  143.52 47.78 0 bottom
C5006  SCD1U25V2KX-GP  [C402H22]  87.13 84.86 90 top
C5501  SCD1U16V2KX-3GP  [C402H22]  51.6 84.12 0 top
C5502  SC4D7U25V5KX-GP  [C805H54]  43.88 82.77 90 bottom
C5503  SC1KP50V2KX-1GP  [C402H22]  46.6 84.15 180 top
C5504  SCD1U25V2KX-GP  [C402H22]  45.74 84.16 180 top
C5505  SCD1U16V2KX-3GP  [C402H22]  52.42 84.12 0 top
C5506  SCD1U16V2KX-3GP  [C402H22]  50.77 84.12 0 top
C5507  SCD1U16V2KX-3GP  [C402H22]  49.95 84.12 0 top
C5508  SCD1U16V2KX-3GP  [C402H22]  63.21 82.81 270 top
C5509  SC1U10V2KX-1GP  [C402H22]  63.21 81.96 90 top
C5510  SCD1U16V2KX-3GP  [C402H22]  49.11 84.12 0 top
C5511  SC4D7U6D3V3KX-GP  [C603H36]  62.89 81.82 90 bottom
C5512  SC4D7U6D3V3KX-GP  [C603H36]  69.44 77.62 180 bottom
C5513  SCD1U16V2KX-3GP  [C402H22]  48.28 84.12 0 top
C5514  SC4D7U6D3V3KX-GP  [C603H36]  69.56 83.07 270 bottom
C5701  SCD1U16V2KX-3GP  [C402H22]  18.32 79.72 270 top
C5702  SCD1U16V2KX-3GP  [C402H22]  18.32 78.91 270 top
C5703  SCD1U16V2KX-3GP  [C402H22]  18.27 77.97 270 top
C5704  SCD1U16V2KX-3GP  [C402H22]  18.27 77.16 270 top
C5705  SCD1U16V2KX-3GP  [C402H22]  18.11 69.83 270 top
C5706  SCD1U16V2KX-3GP  [C402H22]  18.11 69.02 270 top
C5707  SCD1U16V2KX-3GP  [C402H22]  18.11 68.05 270 top
C5708  SCD1U16V2KX-3GP  [C402H22]  18.11 67.24 270 top
C6102  SCD1U16V2KX-3GP  [C402H22]  174.13 94.21 180 top
C6103  SC10U6D3V2MX-GP-U  [C402-TO0D2H28]  173.13 77.83 0 top
C6104  SCD1U16V2KX-3GP  [C402H22]  174.09 77.87 0 top
C6301  SC1U10V2KX-1GP  [C402H22]  114.73 87.1 90 top
C6302  SC4D7U6D3V2MX-GP-U  [C402-TO0D2H26]  114.26 96.09 0 bottom
C6303  SCD1U16V2KX-3GP  [C402H22]  101.44 93.12 90 top
C6304  SC4D7U6D3V2MX-GP-U  [C402-TO0D2H26]  96.25 89.46 180 bottom
C6305  SCD1U16V2KX-3GP  [C402H22]  110.41 92.86 0 top
C6504  SCD1U16V2KX-3GP  [C402H22]  45.03 2.9 0 top
C6505  SCD1U16V2KX-3GP  [C402H22]  46.31 3.34 90 top
C6701  SCD047U16V2KX-1-GP  [C402H22]  7.95 37.69 90 top
C6702  SCD1U16V2KX-3GP  [C402H22]  9.22 37.18 180 top
C6901  SC10U6D3V3MX-GP  [C603H38]  53.77 91.51 270 top
C6902  SCD1U16V2KX-3GP  [C402H22]  54.05 90.43 270 top
CPU1  BRASWELL-GP  [BGA1170M2725H57]  77 53.07 135 bottom
D1901  BAS16-6-GP  [SOT23-2D4-312H44]  77.29 80.92 90 bottom
D2701  BAT54C-7-F-3-GP  [SOT23-2D4-312H48]  127.61 93.54 0 bottom
D4001  LBAS16LT1G-GP  [SOT23-2D4-312H44]  148.04 40.92 180 bottom
D4301  LBAV99LT1G-1-GP  [SOT23-2D4-312H44]  108.83 22.69 180 top
D4302  LBAV99LT1G-1-GP  [SOT23-2D4-312H44]  104.73 18.77 270 top
D4303  LBAV99LT1G-1-GP  [SOT23-2D4-312H44]  104.73 22.7 270 top
D5501  BAT54C-7-F-3-GP  [SOT23-2D4-312H48]  62.39 79.06 180 bottom
D5502  BAT54C-7-F-3-GP  [SOT23-2D4-312H48]  50.38 78.62 270 bottom
D5701  LBAW56LT1G-GP  [SOT23-2D4-312H44]  30.18 81.65 0 bottom
DB1  PAD-ACES-CON10-14-GP  [PAD-87212-1002N]  80.95 8.18 180 top
DCIN1  ACES-CON6-20-GP-U  [50224-0060N-W01]  23 81 0 bottom
EC502  AZ5725-01FDR7G-GP  [SOD882-10D6-1H20]  97 68.61 180 bottom
EC503  AZ5725-01FDR7G-GP  [SOD882-10D6-1H20]  81.29 57.28 315 top
EC504  AZ5725-01FDR7G-GP  [SOD882-10D6-1H20]  81.1 67.29 225 top
EC1001  SC1KP50V2KX-1GP  [C402H22]  76.74 54.51 315 top
EC1002  SC1KP50V2KX-1GP  [C402H22]  62.72 42.9 270 top
EC1003  SCD01U50V2KX-1GP  [C402H22]  51.86 58.62 270 top
EC1004  SC1KP50V2KX-1GP  [C402H22]  59.13 58.98 270 bottom
EC1005  SC1KP50V2KX-1GP  [C402H22]  50.79 66.81 0 top
EC1006  SCD01U50V2KX-1GP  [C402H22]  50.99 72.51 180 top
EC1007  SC1KP50V2KX-1GP  [C402H22]  62.25 80.14 180 top
EC1101  SC1KP50V2KX-1GP  [C402H22]  96.51 57.77 45 bottom
EC1102  SC1KP50V2KX-1GP  [C402H22]  96.57 46.26 135 bottom
EC1103  SC22P50V2JN-4GP  [C402H22]  115.26 85.82 180 top
EC1104  SC22P50V2JN-4GP  [C402H22]  93.68 28.66 270 top
EC1105  SC1KP50V2KX-1GP  [C402H22]  132.49 76.25 0 bottom
EC1106  SC22P50V2JN-4GP  [C402H22]  133.12 59.77 0 bottom
EC1107  SC22P50V2JN-4GP  [C402H22]  132.97 41.57 270 bottom
EC1108  SC22P50V2JN-4GP  [C402H22]  132.45 45.04 180 bottom
EC1201  SC1KP50V2KX-1GP  [C402H22]  130.65 40.24 270 top
EC1202  SC1KP50V2KX-1GP  [C402H22]  129.89 34.03 0 top
EC1203  SC1KP50V2KX-1GP  [C402H22]  130.98 46.55 270 top
EC1204  SC1KP50V2KX-1GP  [C402H22]  130.44 72.09 270 top
EC1205  SC1KP50V2KX-1GP  [C402H22]  126.95 55.63 0 top
EC1206  SC1KP50V2KX-1GP  [C402H22]  119.71 62.56 180 top
EC1801  SC10P50V2JN-4GP  [C402H22]  59.76 58.61 0 top
EC1802  SC10P50V2JN-4GP  [C402H22]  62.71 64.2 90 top
EC1803  SC10P50V2JN-4GP  [C402H22]  65.6 61.75 0 top
EC1808  AZ5725-01FDR7G-GP  [SOD882-10D6-1H20]  64.82 49.3 315 top
EC1809  AZ5725-01FDR7G-GP  [SOD882-10D6-1H20]  58.26 24.76 270 top
EC1810  AZ5725-01FDR7G-GP  [SOD882-10D6-1H20]  63.2 29.92 0 bottom
EC1811  AZ5725-01FDR7G-GP  [SOD882-10D6-1H20]  62.43 45.11 135 bottom
EC1812  AZ5725-01FDR7G-GP  [SOD882-10D6-1H20]  140.23 76.45 180 top
EC1813  AZ5725-01FDR7G-GP  [SOD882-10D6-1H20]  87.29 91.74 90 bottom
EC1814  AZ5725-01FDR7G-GP  [SOD882-10D6-1H20]  57.43 30.29 270 bottom
EC2401  AZ5725-01FDR7G-GP  [SOD882-10D6-1H20]  31.92 61.34 180 top
EC2402  AZ5725-01FDR7G-GP  [SOD882-10D6-1H20]  139.84 52.46 0 bottom
EC2403  AZ5725-01FDR7G-GP  [SOD882-10D6-1H20]  150.15 43.15 90 top
EC2501  SC4D7P50V2BN-GP  [C402H22]  137.96 78.03 270 top
EC2502  SC4D7P50V2BN-GP  [C402H22]  139.55 66.49 180 bottom
EC2503  SC4D7P50V2BN-GP  [C402H22]  140.38 66.48 180 bottom
EC2601  SC33P50V2JN-3GP  [C402H22]  96.13 70.41 0 bottom
EC2602  SC33P50V2JN-3GP  [C402H22]  96.13 68.66 180 bottom
EC2703  SCD1U25V2KX-GP  [C402H22]  142.34 87.42 180 top
EC2704  SCD1U25V2KX-GP  [C402H22]  151.03 97.58 270 top
EC2705  SCD1U25V2KX-GP  [C402H22]  154.15 93.7 90 top
EC2706  SCD1U25V2KX-GP  [C402H22]  131.98 88.24 90 bottom
EC2707  SCD1U25V2KX-GP  [C402H22]  132.17 85.93 270 top
EC2708  SC22P50V2JN-4GP  [C402H22]  138.45 94.09 0 top
EC2709  SC22P50V2JN-4GP  [C402H22]  140.64 95.92 180 top
EC2710  SCD1U25V2KX-GP  [C402H22]  138.13 88.37 90 top
EC2901  SC1KP50V2KX-1GP  [C402H22]  95.55 100.07 0 bottom
EC2902  SC1KP50V2KX-1GP  [C402H22]  95.5 98.06 180 bottom
EC2903  SC1KP50V2KX-1GP  [C402H22]  95.5 96.38 0 bottom
EC2904  SC1KP50V2KX-1GP  [C402H22]  95.5 94.42 180 bottom
EC2905  SC100P50V2JN-3GP  [C402H22]  145.88 91.78 90 top
EC2906  SC100P50V2JN-3GP  [C402H22]  145.96 88.92 90 top
EC2907  SC100P50V2JN-3GP  [C402H22]  139.8 82.1 0 top
EC2908  SC100P50V2JN-3GP  [C402H22]  138.97 82.09 0 top
EC3301  AZ5123-01F-R7G-GP-U  [SOD882-10D6-1H20]  11.88 41.96 90 top
EC3302  AZ5123-01F-R7G-GP-U  [SOD882-10D6-1H20]  19.13 39.1 270 bottom
EC3303  AZ5123-01F-R7G-GP-U  [SOD882-10D6-1H20]  18.47 40.73 270 bottom
EC3304  AZ5123-01F-R7G-GP-U  [SOD882-10D6-1H20]  17.78 42.1 180 top
EC3305  AZ5123-01F-R7G-GP-U  [SOD882-10D6-1H20]  15.04 42.83 180 top
EC3306  AZ5123-01F-R7G-GP-U  [SOD882-10D6-1H20]  12.93 42.85 270 top
EC3307  SC5P50V2CN-2GP  [C402H22]  15.39 41.48 270 top
EC4001  SCD1U16V2KX-3GP  [C402H22]  146.2 44.9 270 bottom
EC4002  SCD1U16V2KX-3GP  [C402H22]  146.2 49.76 270 bottom
EC4003  SCD1U16V2KX-3GP  [C402H22]  148.56 44.87 90 bottom
EC4004  SCD1U16V2KX-3GP  [C402H22]  147.9 49.76 90 bottom
EC4005  AZ5725-01FDR7G-GP  [SOD882-10D6-1H20]  74.26 25.9 180 bottom
EC4006  SCD1U16V2KX-3GP  [C402H22]  17.13 14.05 0 top
EC4301  SC10P50V2JN-4GP  [C402H22]  110.15 20.67 0 top
EC4302  SC10P50V2JN-4GP  [C402H22]  107 20.67 0 top
EC4303  SCD1U25V2KX-GP  [C402H22]  117.42 19.18 90 bottom
EC4304  SCD1U25V2KX-GP  [C402H22]  22.97 76.08 270 top
EC4305  SC10P50V2JN-4GP  [C402H22]  106.75 17.29 270 top
EC4306  SCD1U25V2KX-GP  [C402H22]  22.97 75.27 270 top
EC4307  SC10P50V2JN-4GP  [C402H22]  27.07 68.18 180 top
EC4308  SCD01U50V2KX-1GP  [C402H22]  32.2 24.76 90 top
EC4309  SCD01U50V2KX-1GP  [C402H22]  33.44 55.18 90 top
EC4310  SCD01U50V2KX-1GP  [C402H22]  31.72 52.92 90 top
EC4311  SCD01U50V2KX-1GP  [C402H22]  32.78 17.13 90 top
EC4312  SCD01U50V2KX-1GP  [C402H22]  34.93 5.57 90 top
EC4313  SCD01U50V2KX-1GP  [C402H22]  21.74 6.67 270 top
EC4401  SCD01U50V2KX-1GP  [C402H22]  140.62 26.13 0 bottom
EC4402  SCD1U25V2KX-GP  [C402H22]  36.53 50.02 270 top
EC4403  SCD1U25V2KX-GP  [C402H22]  121.34 14.68 90 top
EC4701  SCD1U50V3KX-GP  [C603H36]  38.65 61.12 180 bottom
EC4801  SCD1U50V3KX-GP  [C603H36]  39.07 71.27 0 bottom
EC5501  SCD1U25V2KX-GP  [C402H22]  36.01 83.26 90 bottom
EC5502  SCD1U25V2KX-GP  [C402H22]  41.39 83.11 270 bottom
EC5503  SCD1U25V2KX-GP  [C402H22]  36.66 60.21 270 top
EC5505  SC22P50V2JN-4GP  [C402H22]  57.08 81.54 90 top
EC5506  SC22P50V2JN-4GP  [C402H22]  55.39 81.54 270 top
EC5507  SC6P50V2CN-1GP  [C402H22]  57.88 86.43 0 top
EC5510  SC33P50V2JN-3GP  [C402H22]  66.36 82.84 90 bottom
EC5701  SCD1U25V2KX-GP  [C402H22]  14.9 80.84 0 top
EC6403  SC100P50V2JN-3GP  [C402H22]  12.49 13.55 90 top
EC6405  SC100P50V2JN-3GP  [C402H22]  8.12 13.57 90 top
EC6427  PESD5V0S1BB-GP-U  [SOD-523-2H26]  5.74 14.61 0 bottom
EC6428  PESD5V0S1BB-GP-U  [SOD-523-2H26]  15.14 15.04 0 bottom
EC6501  SC4D7P50V2BN-GP  [C402H22]  39.92 10.99 90 top
EC6502  SC100P50V2JN-3GP  [C402H22]  38.92 17.1 90 top
EC6503  SC4D7P50V2BN-GP  [C402H22]  38.23 10.99 270 top
EC6504  AZ5725-01FDR7G-GP  [SOD882-10D6-1H20]  40.5 4.66 0 top
EC6505  AZ5725-01FDR7G-GP  [SOD882-10D6-1H20]  40.5 6.26 180 top
EC6506  SC10P50V2JN-4GP  [C402H22]  76.59 16.58 180 bottom
EL4301  -  [0R0402-PAD]  22.92 73.47 0 top
EL4302  -  [0R0402-PAD]  23.74 73.47 0 top
EL4303  -  [0R0402-PAD]  25.36 73.47 0 top
EL4304  -  [0R0402-PAD]  24.55 73.47 0 top
EU3501  AZ1043-04F-R7G-GP  [DFN10G2510H22]  19.77 44.03 270 bottom
EU3505  AZC099-04S-2-GP  [SOT-6H58]  21 49.02 180 bottom
F5501  POLYSW-1D1A24V-GP-U  [POLYSW-4633-UH43]  41.76 79.59 270 bottom
F5502  POLYSW-1D1A6V-9-GP-U  [POLYSW-2114H30]  70.08 80.7 0 bottom
F5701  POLYSW-1D1A6V-9-GP-U  [POLYSW-2114H30]  15.15 79.98 180 bottom
G1801  GAP-OPEN  [CON2O-U]  63.6 44.56 135 bottom
H1  HOLE354R237-GP  [HOLE354R237]  10.3 4.65 0 top
H2  HOLE256R142-OG-1-GP  [HOLE256R142-OG]  142.7 4.65 0 top
H4  HOLE335R197-GP  [HOLE335R197]  74.5 87.85 0 top
H9  HOLE335R197-GP  [HOLE335R197]  69.3 3.05 0 top
HDMI1  SKT-HDMI23-147-GP  [SKT-HDMI23-188125-1-U1]  2.7 77 90 bottom
HS1  STF237R117H67-3-GP  [STF237R117H67]  87.35 33.73 90 bottom
HS2  STF237R117H67-3-GP  [STF237R117H67]  87.35 72.52 180 bottom
HS3  STF237R117H67-3-GP  [STF237R117H67]  66.45 72.52 270 bottom
HS4  STF237R117H67-3-GP  [STF237R117H67]  66.45 33.73 90 bottom
IOBD1  ACES-CON44-1-GP  [51540-04401-W01]  156.6 86.8 270 bottom
KB1  ACES-CON30-14-GP  [50699-03041-001]  90.9 12 180 bottom
LCD1  ACES-CON40-18-GP  [51540-04001-W01]  55.85 87.4 0 bottom
LED1  ACES-CON4-56-GP-U  [51575-00401-W01]  21.5 11 180 bottom
LIDSW1  S-5712ACDL1-M3T1U-GP  [SOT23-2D8-123H52]  3.9 38 180 top
NOREF  *  [unnamed]  124.99 -1.14 0 top
NOREF#2  -  [unnamed]  29.43 212.69 0 top
NOREF#3  -  [#2]  5.87 194.52 180 top
NOREF#4  -  [unnamed]  92.05 -0.68 0 top
NOREF#5  -  [unnamed]  175.33 212.82 180 top
NOREF#6  -  [#2]  163.28 99.99 0 top
NOREF#7  *  [unnamed]  167.72 98.22 0 top
NOREF#8  -  [#2]  0 11 0 top
NOREF#9  -  [#2]  0 11 0 top
NOREF#10  -  [unnamed]  149.47 -4.69 0 top
NOREF#11  -  [#2]  27.11 95.29 0 top
NOREF#12  -  [#2]  0 11 0 top
NOREF#13  -  [#2]  18.39 1.7 0 top
NOREF#14  -  [unnamed]  163.18 111.4 180 top
NOREF#15  -  [#2]  45.36 39.85 0 top
NOREF#16  -  [#2]  160.51 206.3 180 top
NOREF#17  *  [unnamed]  3.86 8.72 0 top
NOREF#18  -  [#2]  70.35 -3.54 0 top
NOREF#19  -  [#2]  0 11 0 top
NOREF#20  *  [unnamed]  133.87 3.12 0 top
NOREF#21  -  [#2]  178.82 111.55 90 top
NOREF#22  *  [unnamed]  39.74 210.24 180 top
NOREF#23  -  [#2]  0 11 0 top
NOREF#24  -  [#2]  79.66 -7.9 0 top
NOREF#25  -  [#2]  108.33 45.24 0 top
NOREF#26  -  [unnamed]  3 3 0 top
NOREF#27  -  [#2]  0 -9.4 0 top
NOREF#28  -  [unnamed]  3.57 -4.82 0 top
NOREF#29  -  [#2]  173.03 13.48 0 top
NOREF#30  -  [unnamed]  15.72 96.6 0 top
NOREF#31  -  [#2]  0.08 96.45 270 top
NOREF#32  -  [#2]  0 11 0 top
NOREF#33  *  [unnamed]  6.6 -1.81 0 top
NOREF#34  -  [#2]  150.34 72.9 180 bottom
NOREF#35  *  [unnamed]  39.74 210.24 0 bottom
NOREF#36  *  [unnamed]  3.86 8.72 180 bottom
NOREF#37  *  [unnamed]  6.6 -1.81 180 bottom
NOREF#38  -  [#2]  108.24 81.4 180 bottom
NOREF#39  -  [#2]  87.12 -3.54 180 bottom
NOREF#40  -  [#2]  107.06 35.46 180 bottom
NOREF#41  *  [unnamed]  133.87 3.12 180 bottom
NOREF#42  *  [unnamed]  167.72 98.22 180 bottom
NOREF#43  *  [unnamed]  124.99 -1.14 180 bottom
PC1009  SC22U6D3V3MX-1-GP  [C603H40]  75.12 51.51 45 top
PC1010  SC22U6D3V3MX-1-GP  [C603H40]  81.69 80.27 270 top
PC1011  SC22U6D3V3MX-1-GP  [C603H40]  81.69 81.54 270 top
PC1012  SC22U6D3V3MX-1-GP  [C603H40]  69.93 51.39 315 top
PC1014  SC22U6D3V3MX-1-GP  [C603H40]  72.19 49.47 315 top
PC1031  SC10U6D3V2MX-GP-U  [C402-TO0D2H28]  54.58 66.88 0 top
PC1040  SC22U6D3V3MX-1-GP  [C603H40]  82.82 50.77 45 top
PC1041  SC22U6D3V3MX-1-GP  [C603H40]  77.68 51.48 315 top
PC1042  SC22U6D3V3MX-1-GP  [C603H40]  59.39 61.32 270 bottom
PC1043  SC10U6D3V2MX-GP-U  [C402-TO0D2H28]  55.55 66.88 0 top
PC1044  SC1U10V2KX-1GP  [C402H22]  52.65 66.88 0 top
PC1045  SC10U6D3V2MX-GP-U  [C402-TO0D2H28]  51.69 66.88 0 top
PC1046  SC10U6D3V2MX-GP-U  [C402-TO0D2H28]  53.62 66.88 0 top
PC1048  SC22U6D3V3MX-1-GP  [C603H40]  59.39 60.05 270 bottom
PC1051  SC22U6D3V3MX-1-GP  [C603H40]  81.62 71.41 90 bottom
PC1052  SC22U6D3V3MX-1-GP  [C603H40]  81.62 72.68 90 bottom
PC1053  SC22U6D3V3MX-1-GP  [C603H40]  81.54 77.73 270 top
PC1054  SC22U6D3V3MX-1-GP  [C603H40]  81.54 79 270 top
PC1055  SC22U6D3V3MX-1-GP  [C603H40]  82.35 70.11 90 bottom
PC1058  SC22U6D3V3MX-1-GP  [C603H40]  59.39 62.59 270 bottom
PC1059  SC22U6D3V3MX-1-GP  [C603H40]  80.03 49.11 315 top
PC1060  SC22U6D3V3MX-1-GP  [C603H40]  79.74 53.81 135 top
PC1061  SC22U6D3V3MX-1-GP  [C603H40]  79.11 50.04 315 top
PC1062  SC22U6D3V3MX-1-GP  [C603H40]  78.03 57.7 135 top
PC1063  SC22U6D3V3MX-1-GP  [C603H40]  60.14 73.8 270 bottom
PC1064  SC22U6D3V3MX-1-GP  [C603H40]  73.06 56.07 225 top
PC1065  SC22U6D3V3MX-1-GP  [C603H40]  78.93 56.8 135 top
PC1066  SC22U6D3V3MX-1-GP  [C603H40]  56.87 62.77 180 top
PC1067  SC22U6D3V3MX-1-GP  [C603H40]  55.6 62.77 180 top
PC1068  SC22U6D3V3MX-1-GP  [C603H40]  59.39 63.88 270 bottom
PC1069  SC22U6D3V3MX-1-GP  [C603H40]  54.33 62.77 180 top
PC1070  SC22U6D3V3MX-1-GP  [C603H40]  53.33 72.62 180 top
PC1071  SC22U6D3V3MX-1-GP  [C603H40]  52.06 72.62 180 top
PC1072  SC22U6D3V3MX-1-GP  [C603H40]  58.43 72.59 180 top
PC1073  SC22U6D3V3MX-1-GP  [C603H40]  57.94 66.73 0 top
PC1074  SC22U6D3V3MX-1-GP  [C603H40]  60.14 71.21 270 bottom
PC1075  SC22U6D3V3MX-1-GP  [C603H40]  60.14 69.94 270 bottom
PC1076  SC22U6D3V3MX-1-GP  [C603H40]  60.14 68.67 270 bottom
PC1077  SC22U6D3V3MX-1-GP  [C603H40]  60.14 72.48 270 bottom
PC1078  SC22U6D3V3MX-1-GP  [C603H40]  74.21 58.51 225 top
PC1079  SC22U6D3V3MX-1-GP  [C603H40]  73.84 57.08 225 top
PC1080  SC22U6D3V3MX-1-GP  [C603H40]  56.67 66.73 0 top
PC1118  SC22U6D3V3MX-1-GP  [C603H40]  73.89 72.91 135 bottom
PC1119  SC22U6D3V3MX-1-GP  [C603H40]  95.28 56.64 45 bottom
PC1120  SC22U6D3V3MX-1-GP  [C603H40]  96.18 47.37 135 bottom
PC1122  SC22U6D3V3MX-1-GP  [C603H40]  78.11 74.24 315 bottom
PC1123  SC22U6D3V3MX-1-GP  [C603H40]  96.14 49.18 135 bottom
PC1124  SC22U6D3V3MX-1-GP  [C603H40]  79.03 73.32 315 bottom
PC4301  SC1U50V5ZY-1-GP-U  [C805H58]  24.8 67.85 180 bottom
PC4302  SCD1U25V2KX-GP  [C402H22]  21.27 70.09 270 top
PC4303  SCD01U50V2KX-1GP  [C402H22]  139.53 17.26 90 bottom
PC4304  SCD01U50V2KX-1GP  [C402H22]  139.53 19 90 bottom
PC4305  SCD01U50V2KX-1GP  [C402H22]  139.53 18.12 90 bottom
PC4306  SC10U25V5KX-GP  [C805H56]  139.42 15.8 90 bottom
PC4401  SCD1U50V3KX-GP  [C603H36]  127.57 11.57 90 bottom
PC4402  SCD1U25V2KX-GP  [C402H22]  127.63 14.58 180 top
PC4403  SC1U25V3KX-1-GP  [C603H36]  128.67 15.87 0 bottom
PC4404  SC1U25V3KX-1-GP  [C603H36]  127.4 15.87 0 bottom
PC4406  SC10U25V5KX-GP  [C805H56]  137.47 26.14 0 bottom
PC4407  SC1U25V3KX-1-GP  [C603H36]  134.49 16.17 180 top
PC4408  SC4D7U25V5KX-GP  [C805H54]  139.28 26.14 0 bottom
PC4409  SCD1U50V3KX-GP  [C603H36]  140.35 21.72 180 bottom
PC4410  SCD47U25V3KX-1GP  [C603H36]  128.74 15.87 180 top
PC4411  SCD047U25V2KX-GP  [C402H22]  131.54 16.2 180 bottom
PC4412  SCD01U50V2KX-1GP  [C402H22]  130.45 10.57 270 bottom
PC4413  SC3300P50V3KX-1GP  [C603H36]  132.43 16.08 90 top
PC4415  SC10U25V5KX-GP  [C805H56]  115.36 23.02 0 bottom
PC4416  SC10U25V5KX-GP  [C805H56]  111.68 23.02 0 bottom
PC4417  SC10U25V5KX-GP  [C805H56]  124.76 16.87 270 bottom
PC4418  SC10U25V5KX-GP  [C805H56]  113.52 23.02 0 bottom
PC4419  SCD1U50V3KX-GP  [C603H36]  122.66 18.41 270 bottom
PC4420  SCD1U25V2KX-GP  [C402H22]  135.08 12.66 90 bottom
PC4421  SCD1U25V2KX-GP  [C402H22]  136.33 12.32 180 bottom
PC4422  SC100P50V2JN-3GP  [C402H22]  131.85 10.32 0 bottom
PC4423  SCD1U25V2KX-GP  [C402H22]  135.08 11.84 90 bottom
PC4424  SCD1U25V2KX-GP  [C402H22]  141.56 29.1 0 bottom
PC4425  SCD01U50V2KX-1GP  [C402H22]  149.25 15.31 270 top
PC4426  SC10U25V5KX-GP  [C805H56]  138.79 21.53 180 bottom
PC4427  SC1U25V3KX-1-GP  [C603H36]  146.54 28.48 180 bottom
PC4431  SC1U25V3KX-1-GP  [C603H36]  144.7 25.41 270 bottom
PC4433  SCD47U6D3V2KX-GP  [C402H22]  146.82 33.7 90 bottom
PC4434  SC1U25V3KX-1-GP  [C603H36]  133.07 31.22 0 bottom
PC4501  SCD1U25V2KX-GP  [C402H22]  39.21 34.34 0 bottom
PC4502  SC10U25V5KX-GP  [C805H56]  40.53 34.35 0 bottom
PC4503  SC10U25V5KX-GP  [C805H56]  42.33 34.35 0 bottom
PC4504  SC10U25V5KX-GP  [C805H56]  44.13 34.35 0 bottom
PC4505  SC10U25V5KX-GP  [C805H56]  45.54 21.46 180 bottom
PC4506  SCD1U25V2KX-GP  [C402H22]  36.53 32.16 0 top
PC4507  SCD1U16V2KX-3GP  [C402H22]  46.92 17.05 180 bottom
PC4508  SCD1U16V2KX-3GP  [C402H22]  43.39 26.79 180 bottom
PC4509  SC22U6D3V5MX-2GP  [C805H58]  26.58 27.89 180 bottom
PC4510  SC22U6D3V5MX-2GP  [C805H58]  28.39 27.89 180 bottom
PC4511  SC22U6D3V5MX-2GP  [C805H58]  28.12 31.66 0 bottom
PC4512  SC22U6D3V5MX-2GP  [C805H58]  26.32 31.66 0 bottom
PC4513  SCD1U16V2KX-3GP  [C402H22]  25.26 27.74 180 bottom
PC4514  SC22U6D3V5MX-2GP  [C805H58]  26.54 22.94 0 bottom
PC4515  SC22U6D3V5MX-2GP  [C805H58]  24.64 22.94 0 bottom
PC4516  SC22U6D3V5MX-2GP  [C805H58]  28.45 22.94 0 bottom
PC4517  SC22U6D3V5MX-2GP  [C805H58]  25.98 17.63 180 bottom
PC4518  SCD1U16V2KX-3GP  [C402H22]  24.6 17.38 180 bottom
PC4519  SC10U25V5KX-GP  [C805H56]  41.4 24.79 90 bottom
PC4520  SC4D7U25V5KX-GP  [C805H54]  40.95 15.88 180 bottom
PC4521  SCD1U25V2KX-GP  [C402H22]  38.21 23.34 0 top
PC4522  SCD1U25V2KX-GP  [C402H22]  41.38 23.48 90 bottom
PC4523  SC10U25V5KX-GP  [C805H56]  47.67 24 270 bottom
PC4524  SC2D2U10V3KX-1GP  [C603H36]  38.58 18.47 180 bottom
PC4525  SC1KP50V2KX-1GP  [C402H22]  40.78 26.79 180 bottom
PC4526  SC1KP50V2KX-1GP  [C402H22]  42.25 16.4 0 top
PC4527  SC22U6D3V5MX-2GP  [C805H58]  27.83 17.63 180 bottom
PC4528  SC10U25V5KX-GP  [C805H56]  47.67 25.82 270 bottom
PC4529  SC10U25V5KX-GP  [C805H56]  45.94 34.35 0 bottom
PC4530  SCD1U16V2KX-3GP  [C402H22]  42.58 26.79 180 bottom
PC4531  SCD1U16V2KX-3GP  [C402H22]  46.08 17.05 180 bottom
PC4534  SCD1U25V2KX-GP  [C402H22]  48.2 18.35 270 bottom
PC4535  SC4D7U6D3V3KX-GP  [C603H36]  37.86 26.61 180 bottom
PC4538  SCD1U25V2KX-GP  [C402H22]  45.67 28.13 0 bottom
PC4601  SC470P50V2KX-3GP  [C402H22]  22.92 54.87 180 top
PC4602  SC100P50V2JN-3GP  [C402H22]  24.44 55.33 0 bottom
PC4603  SC1KP50V2KX-1GP  [C402H22]  28.55 52.35 270 bottom
PC4604  SC1U10V2KX-1GP  [C402H22]  25.06 59.91 0 bottom
PC4605  SC1KP50V2KX-1GP  [C402H22]  22.27 59.43 90 top
PC4606  SC2200P50V2KX-2GP  [C402H22]  22.85 57.37 0 top
PC4607  SC100P50V2JN-3GP  [C402H22]  26.8 52.43 90 bottom
PC4608  SC470P50V2KX-3GP  [C402H22]  22.98 51.45 90 top
PC4609  SCD22U25V3KX-GP  [C603H40]  33.45 58.12 270 bottom
PC4610  SCD01U50V2KX-1GP  [C402H22]  32.7 60.89 180 bottom
PC4611  SC2D2U10V3KX-1GP  [C603H36]  30.75 52.9 180 bottom
PC4612  SC1KP50V2KX-1GP  [C402H22]  26.8 53.27 90 bottom
PC4613  SCD022U25V2KX-GP  [C402H22]  24.24 53.58 0 top
PC4614  SCD1U16V2KX-3GP  [C402H22]  22.69 61.92 270 top
PC4615  SCD1U16V2KX-3GP  [C402H22]  32.45 64.36 90 top
PC4617  SCD1U16V2KX-3GP  [C402H22]  32.8 56 90 bottom
PC4618  SCD1U16V2KX-3GP  [C402H22]  32.79 61.32 180 top
PC4619  SCD1U16V2KX-3GP  [C402H22]  21 59.5 0 top
PC4620  SCD1U16V2KX-3GP  [C402H22]  21 61.17 180 top
PC4702  SC10U25V5KX-GP  [C805H56]  35.27 61.37 180 bottom
PC4705  SC10U25V5KX-GP  [C805H56]  37.07 61.37 180 bottom
PC4706  SC22U6D3V3MX-1-GP  [C603H40]  75.73 53.42 225 top
PC4707  SC22U6D3V3MX-1-GP  [C603H40]  53.06 62.77 180 top
